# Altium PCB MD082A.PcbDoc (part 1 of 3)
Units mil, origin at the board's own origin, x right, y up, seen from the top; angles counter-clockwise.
Board outline 3650 x 4750 mil, 4 copper layers (Top Layer, GND Layer, Power Layer, Bottom Layer), stack 61.2 mil thick; 201 components, 105 nets, 514 pads, 1209 vias.
Unrouted connection lines stored in the file: 46.
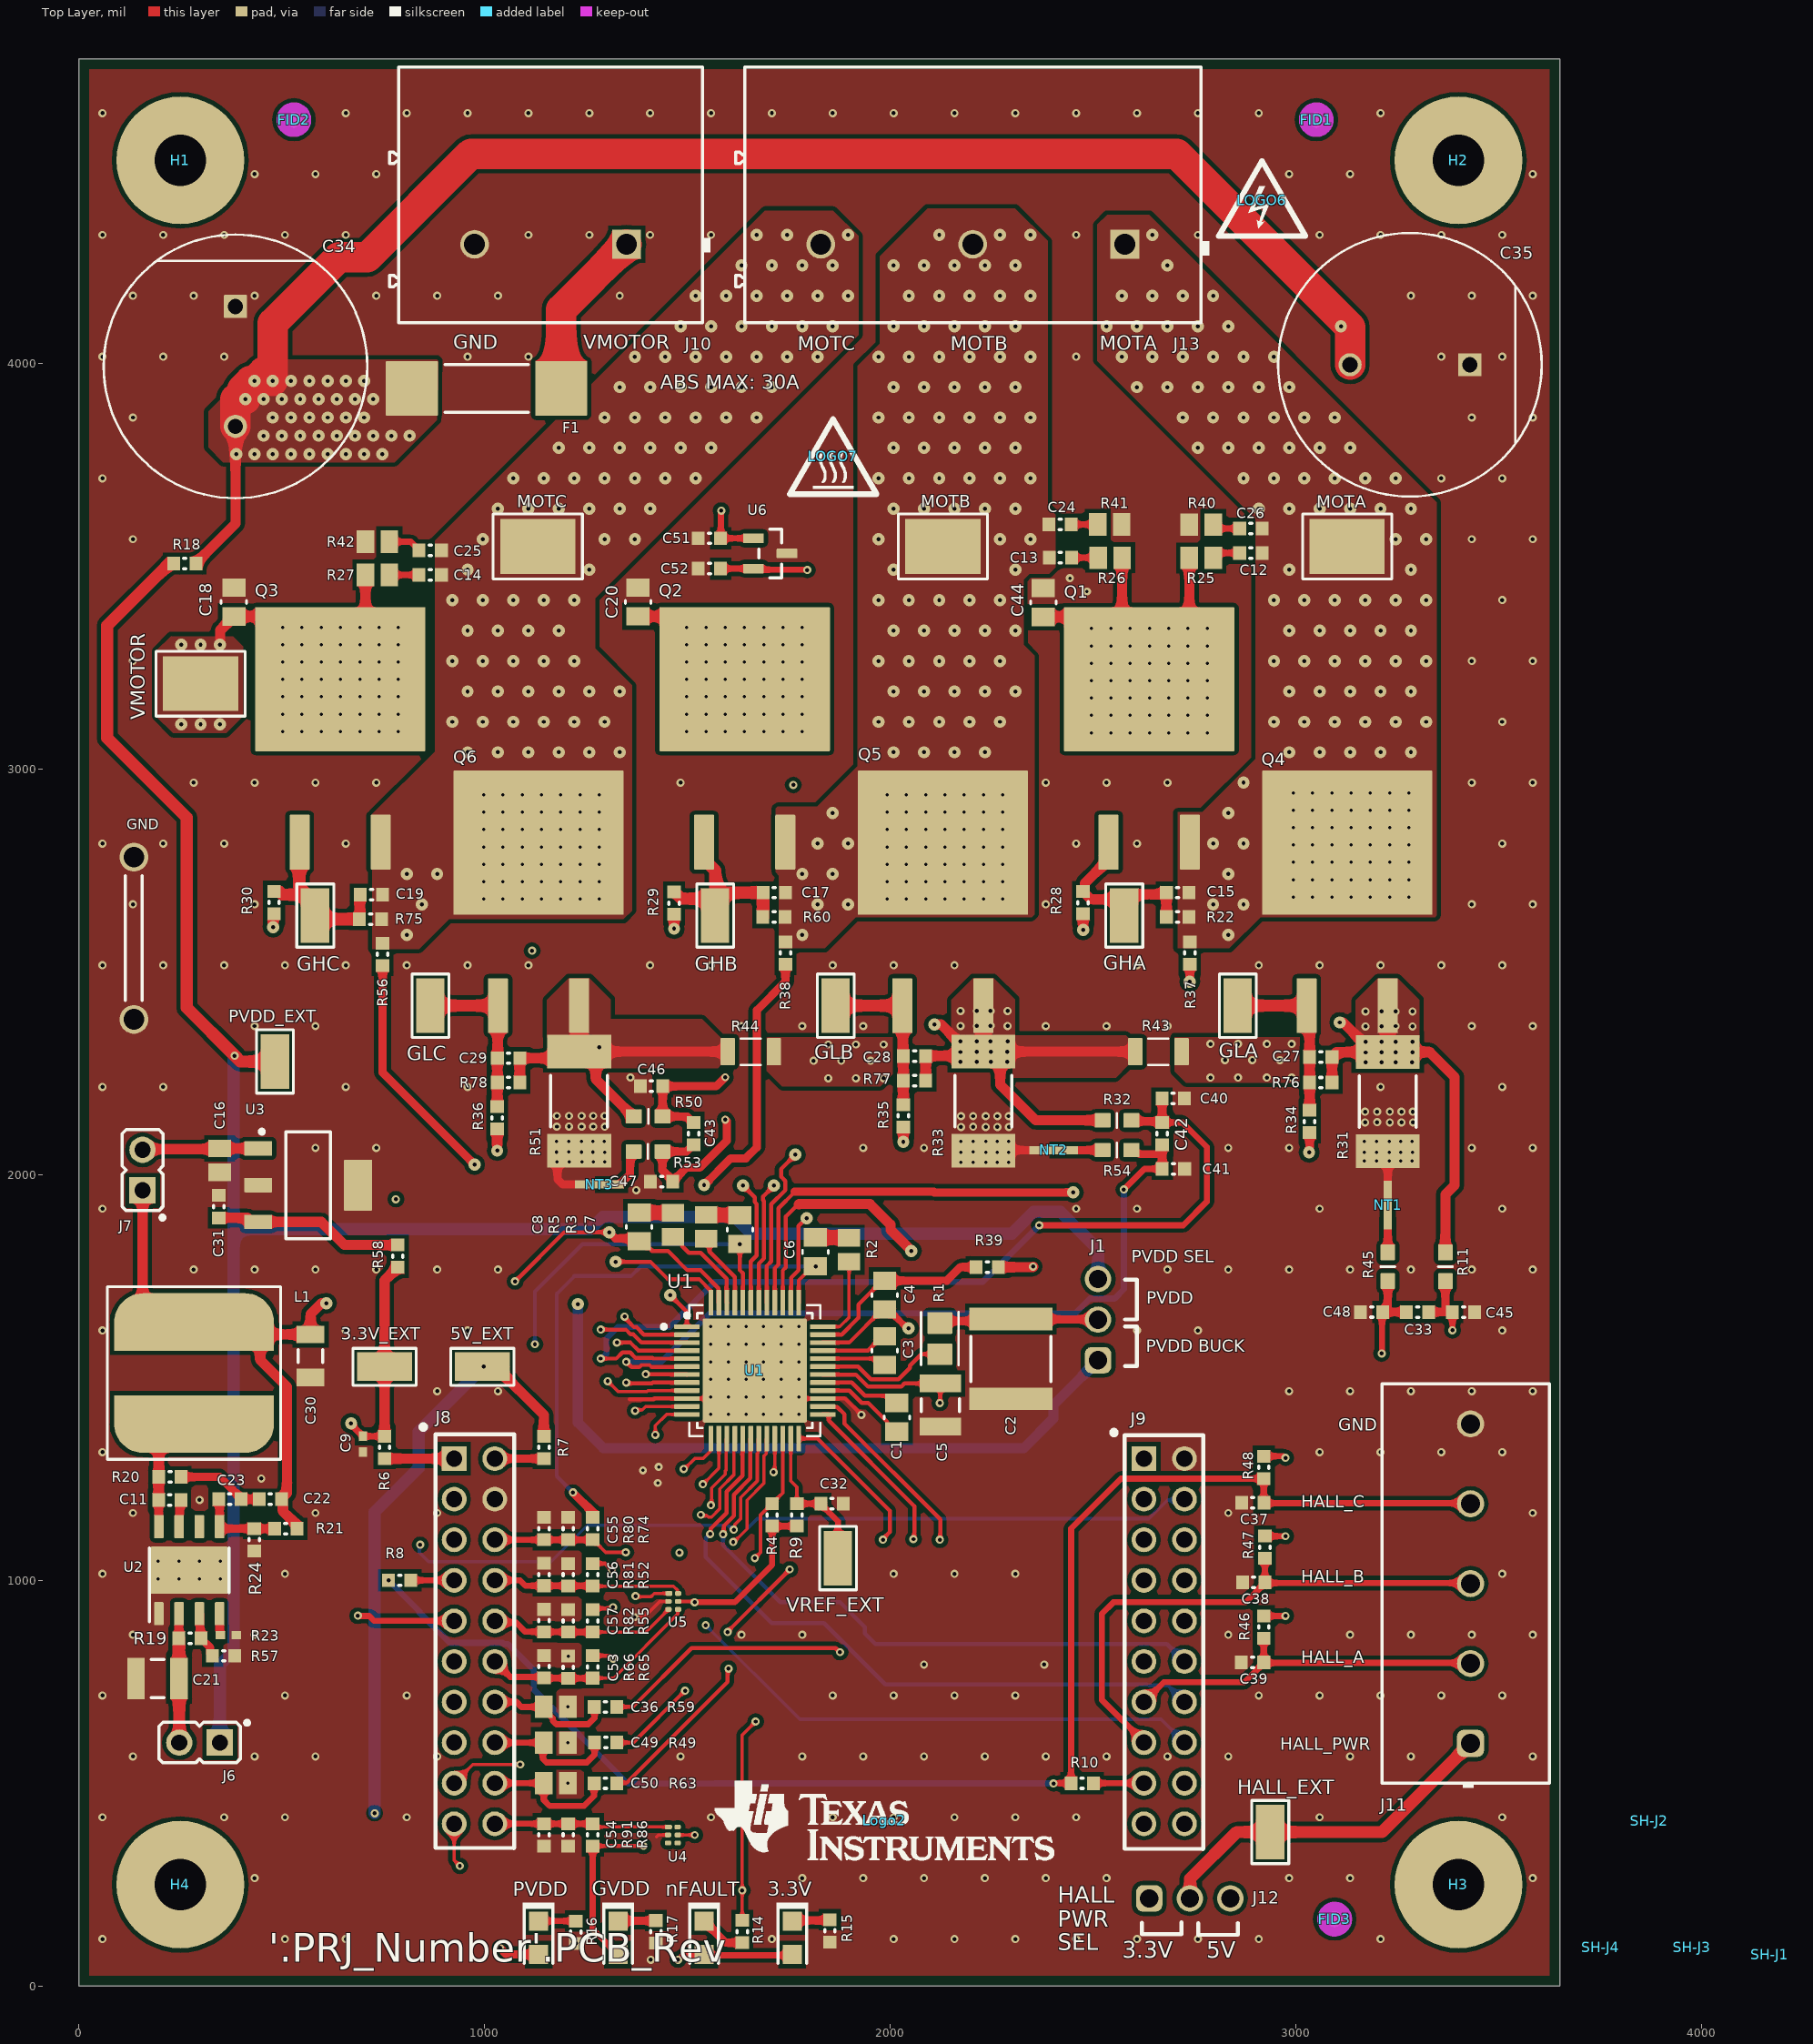
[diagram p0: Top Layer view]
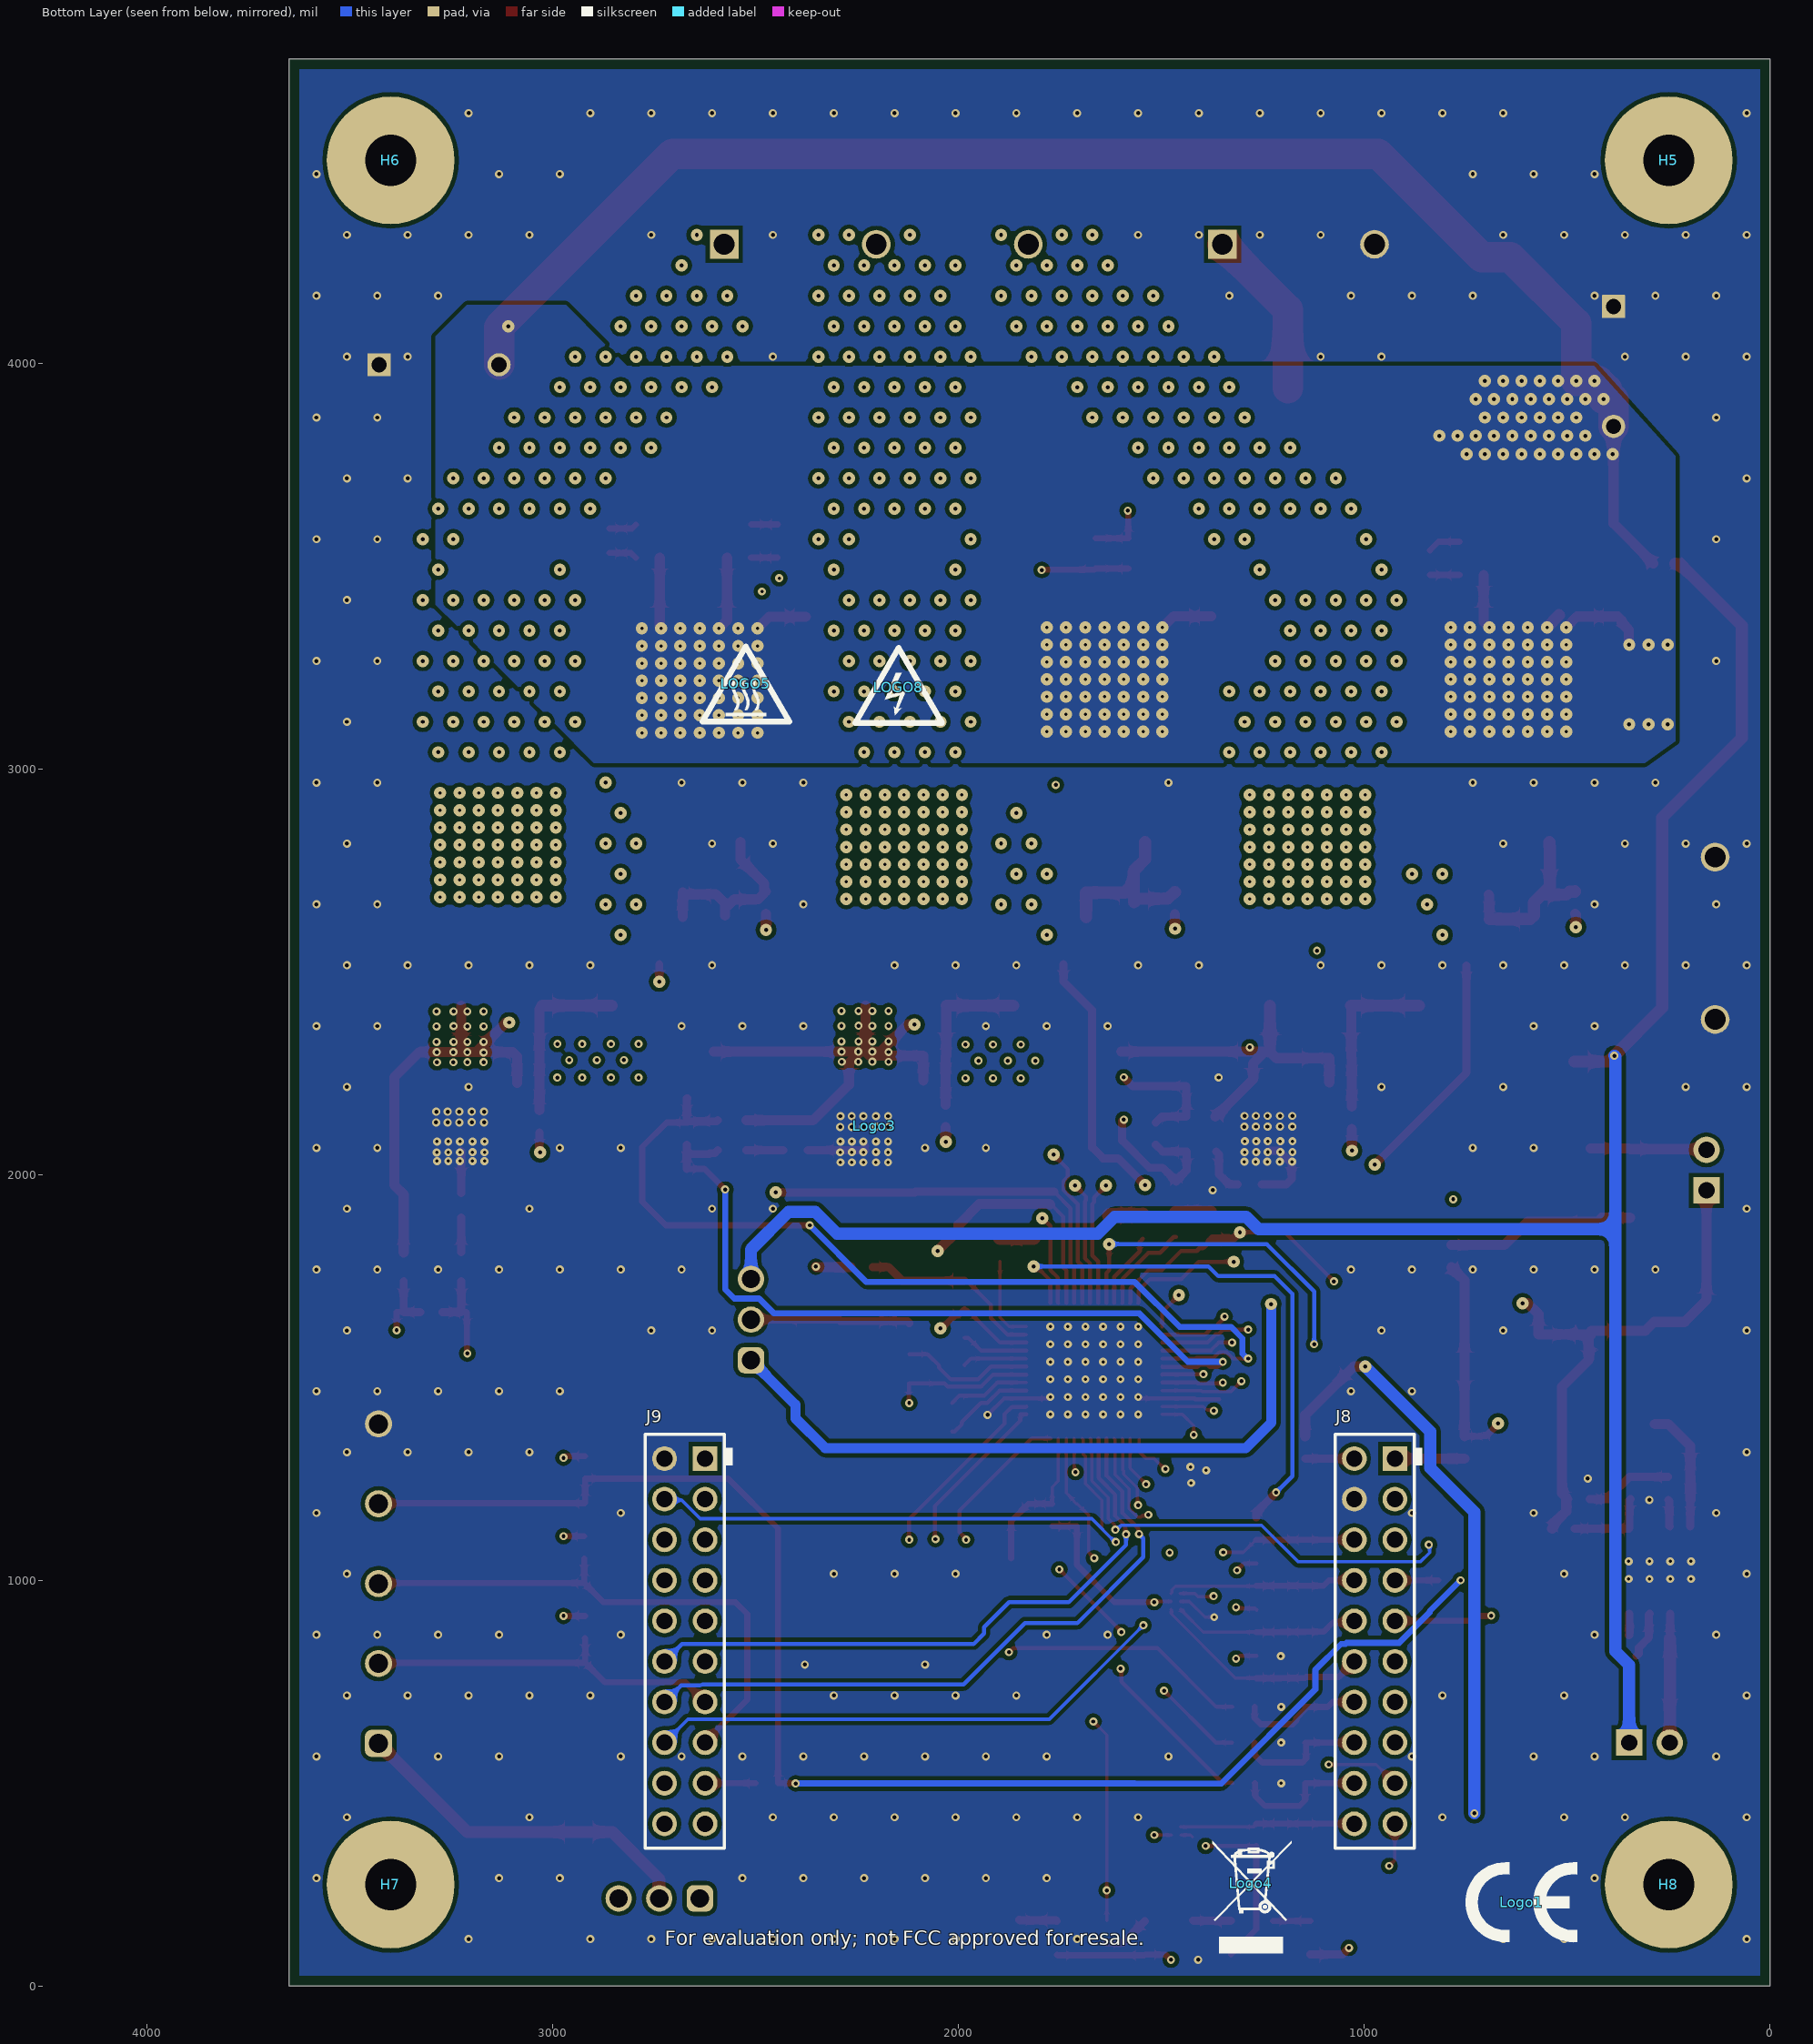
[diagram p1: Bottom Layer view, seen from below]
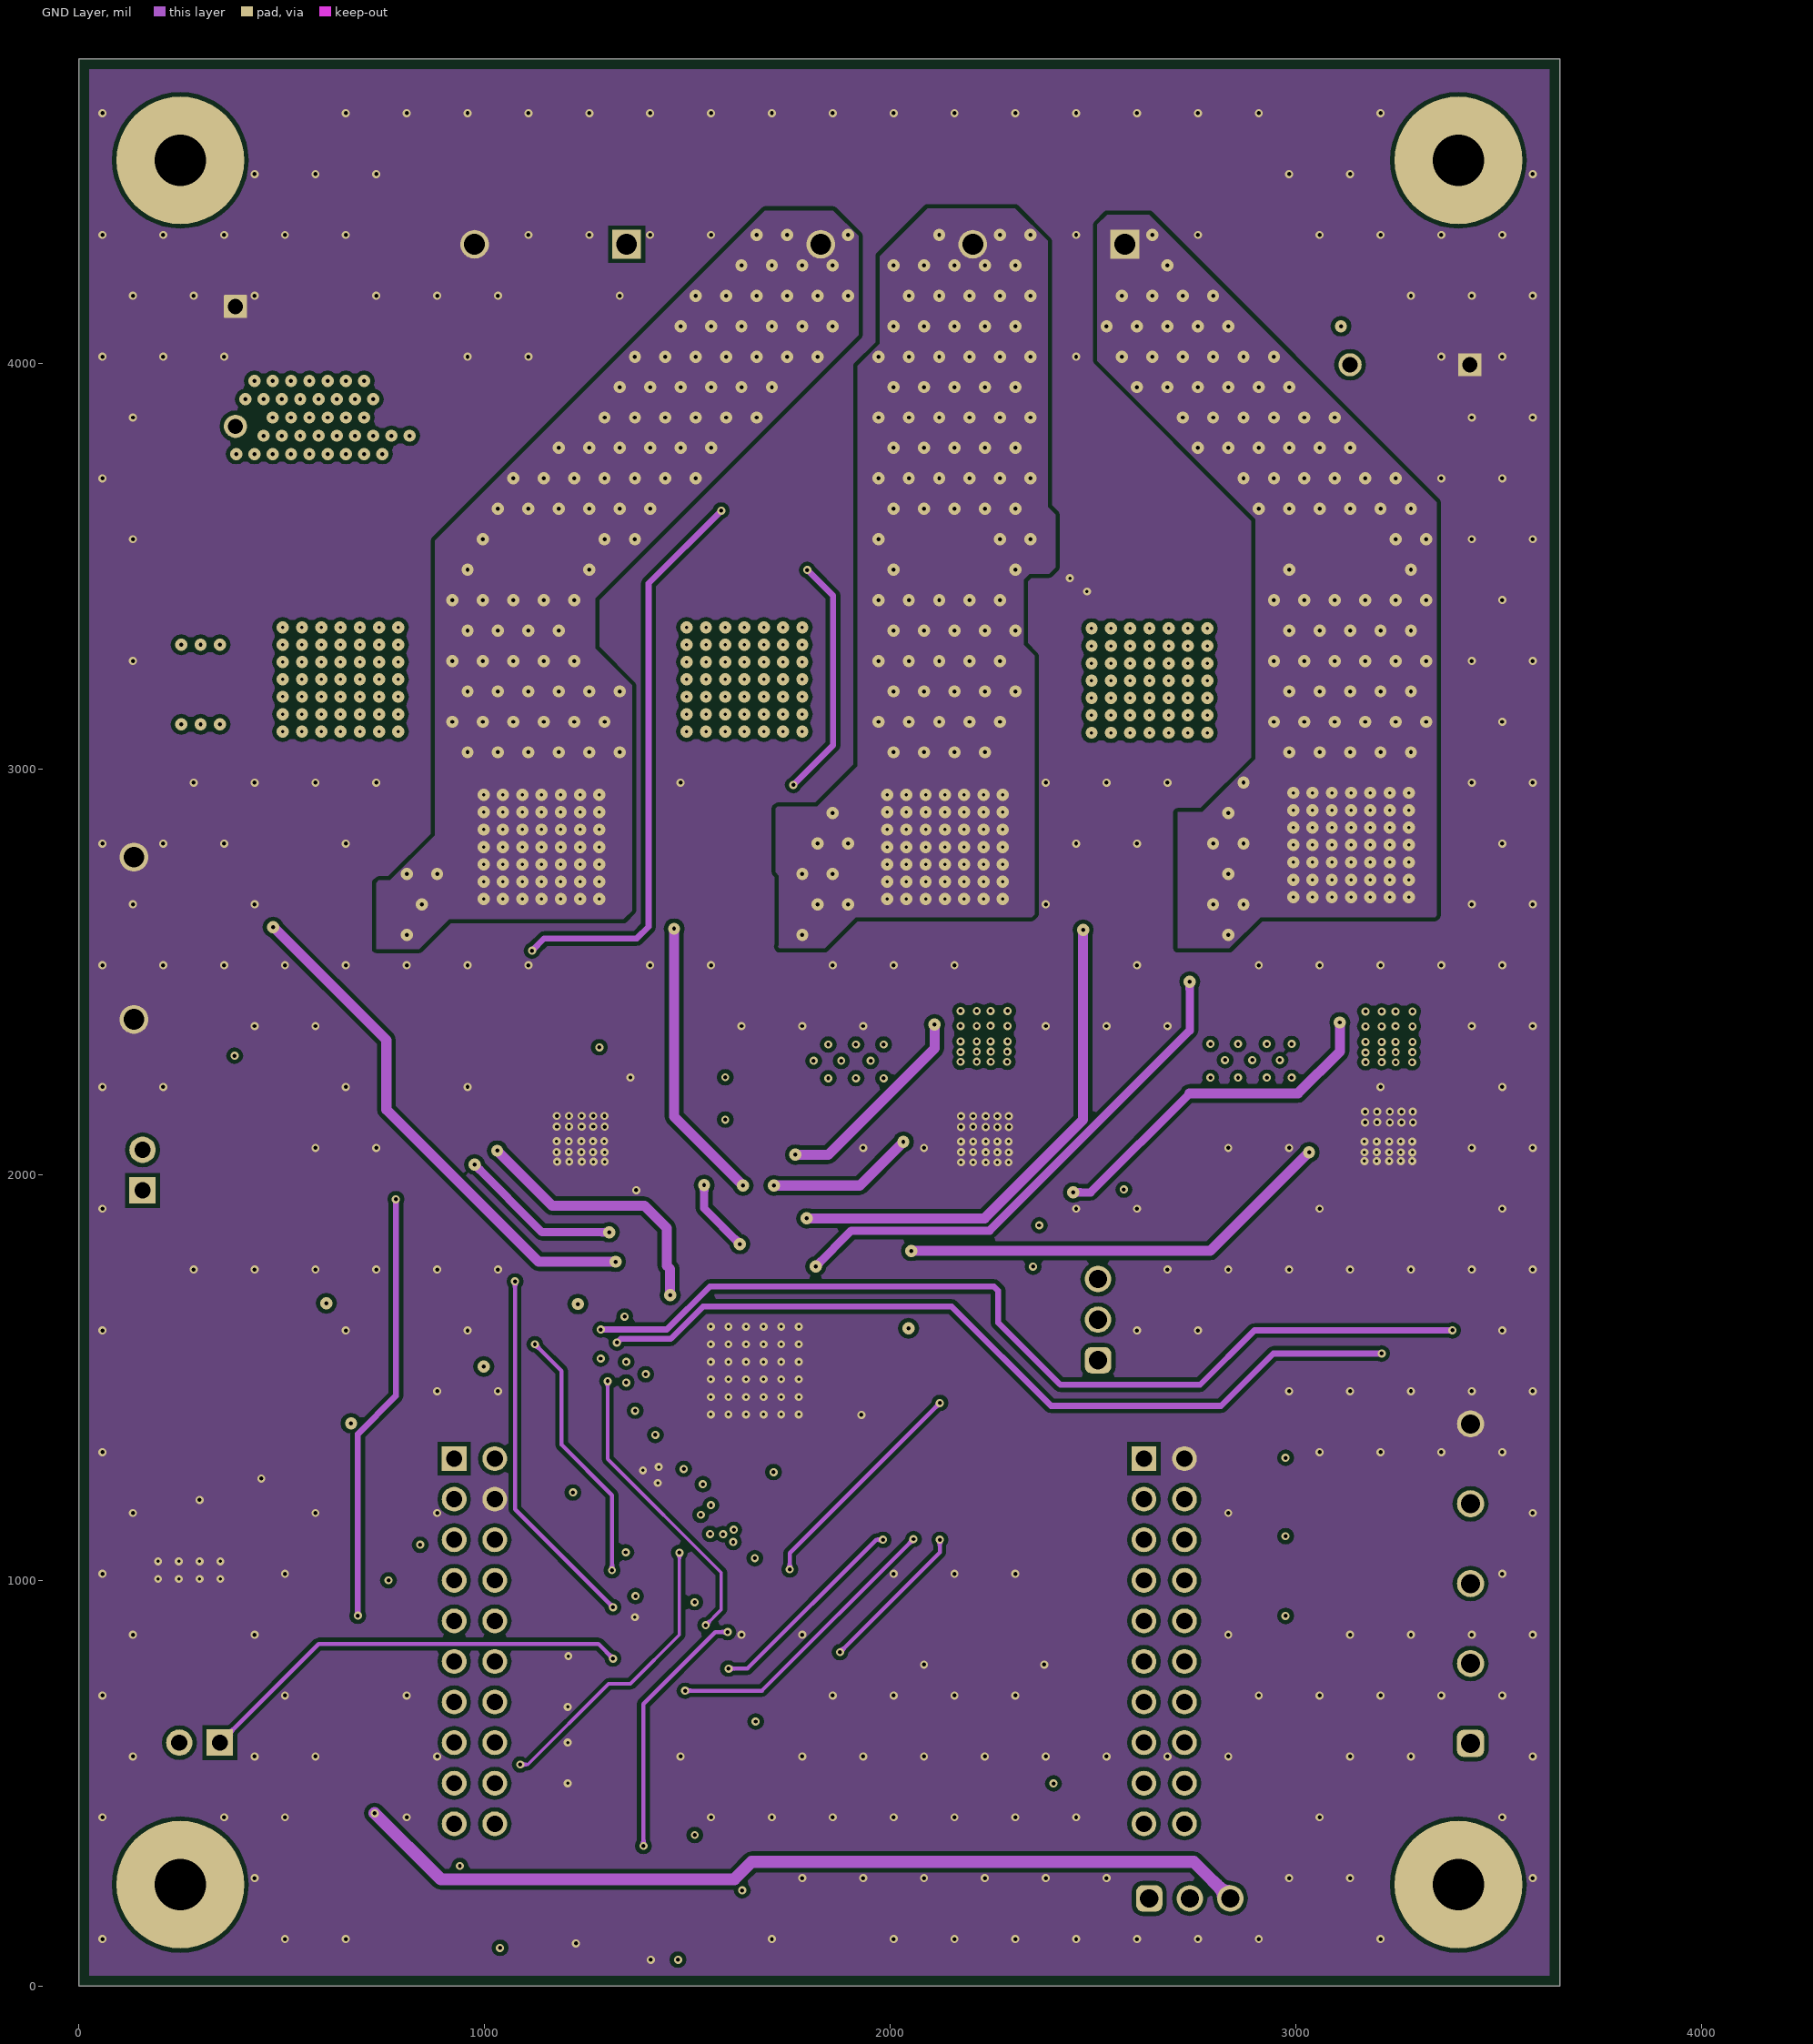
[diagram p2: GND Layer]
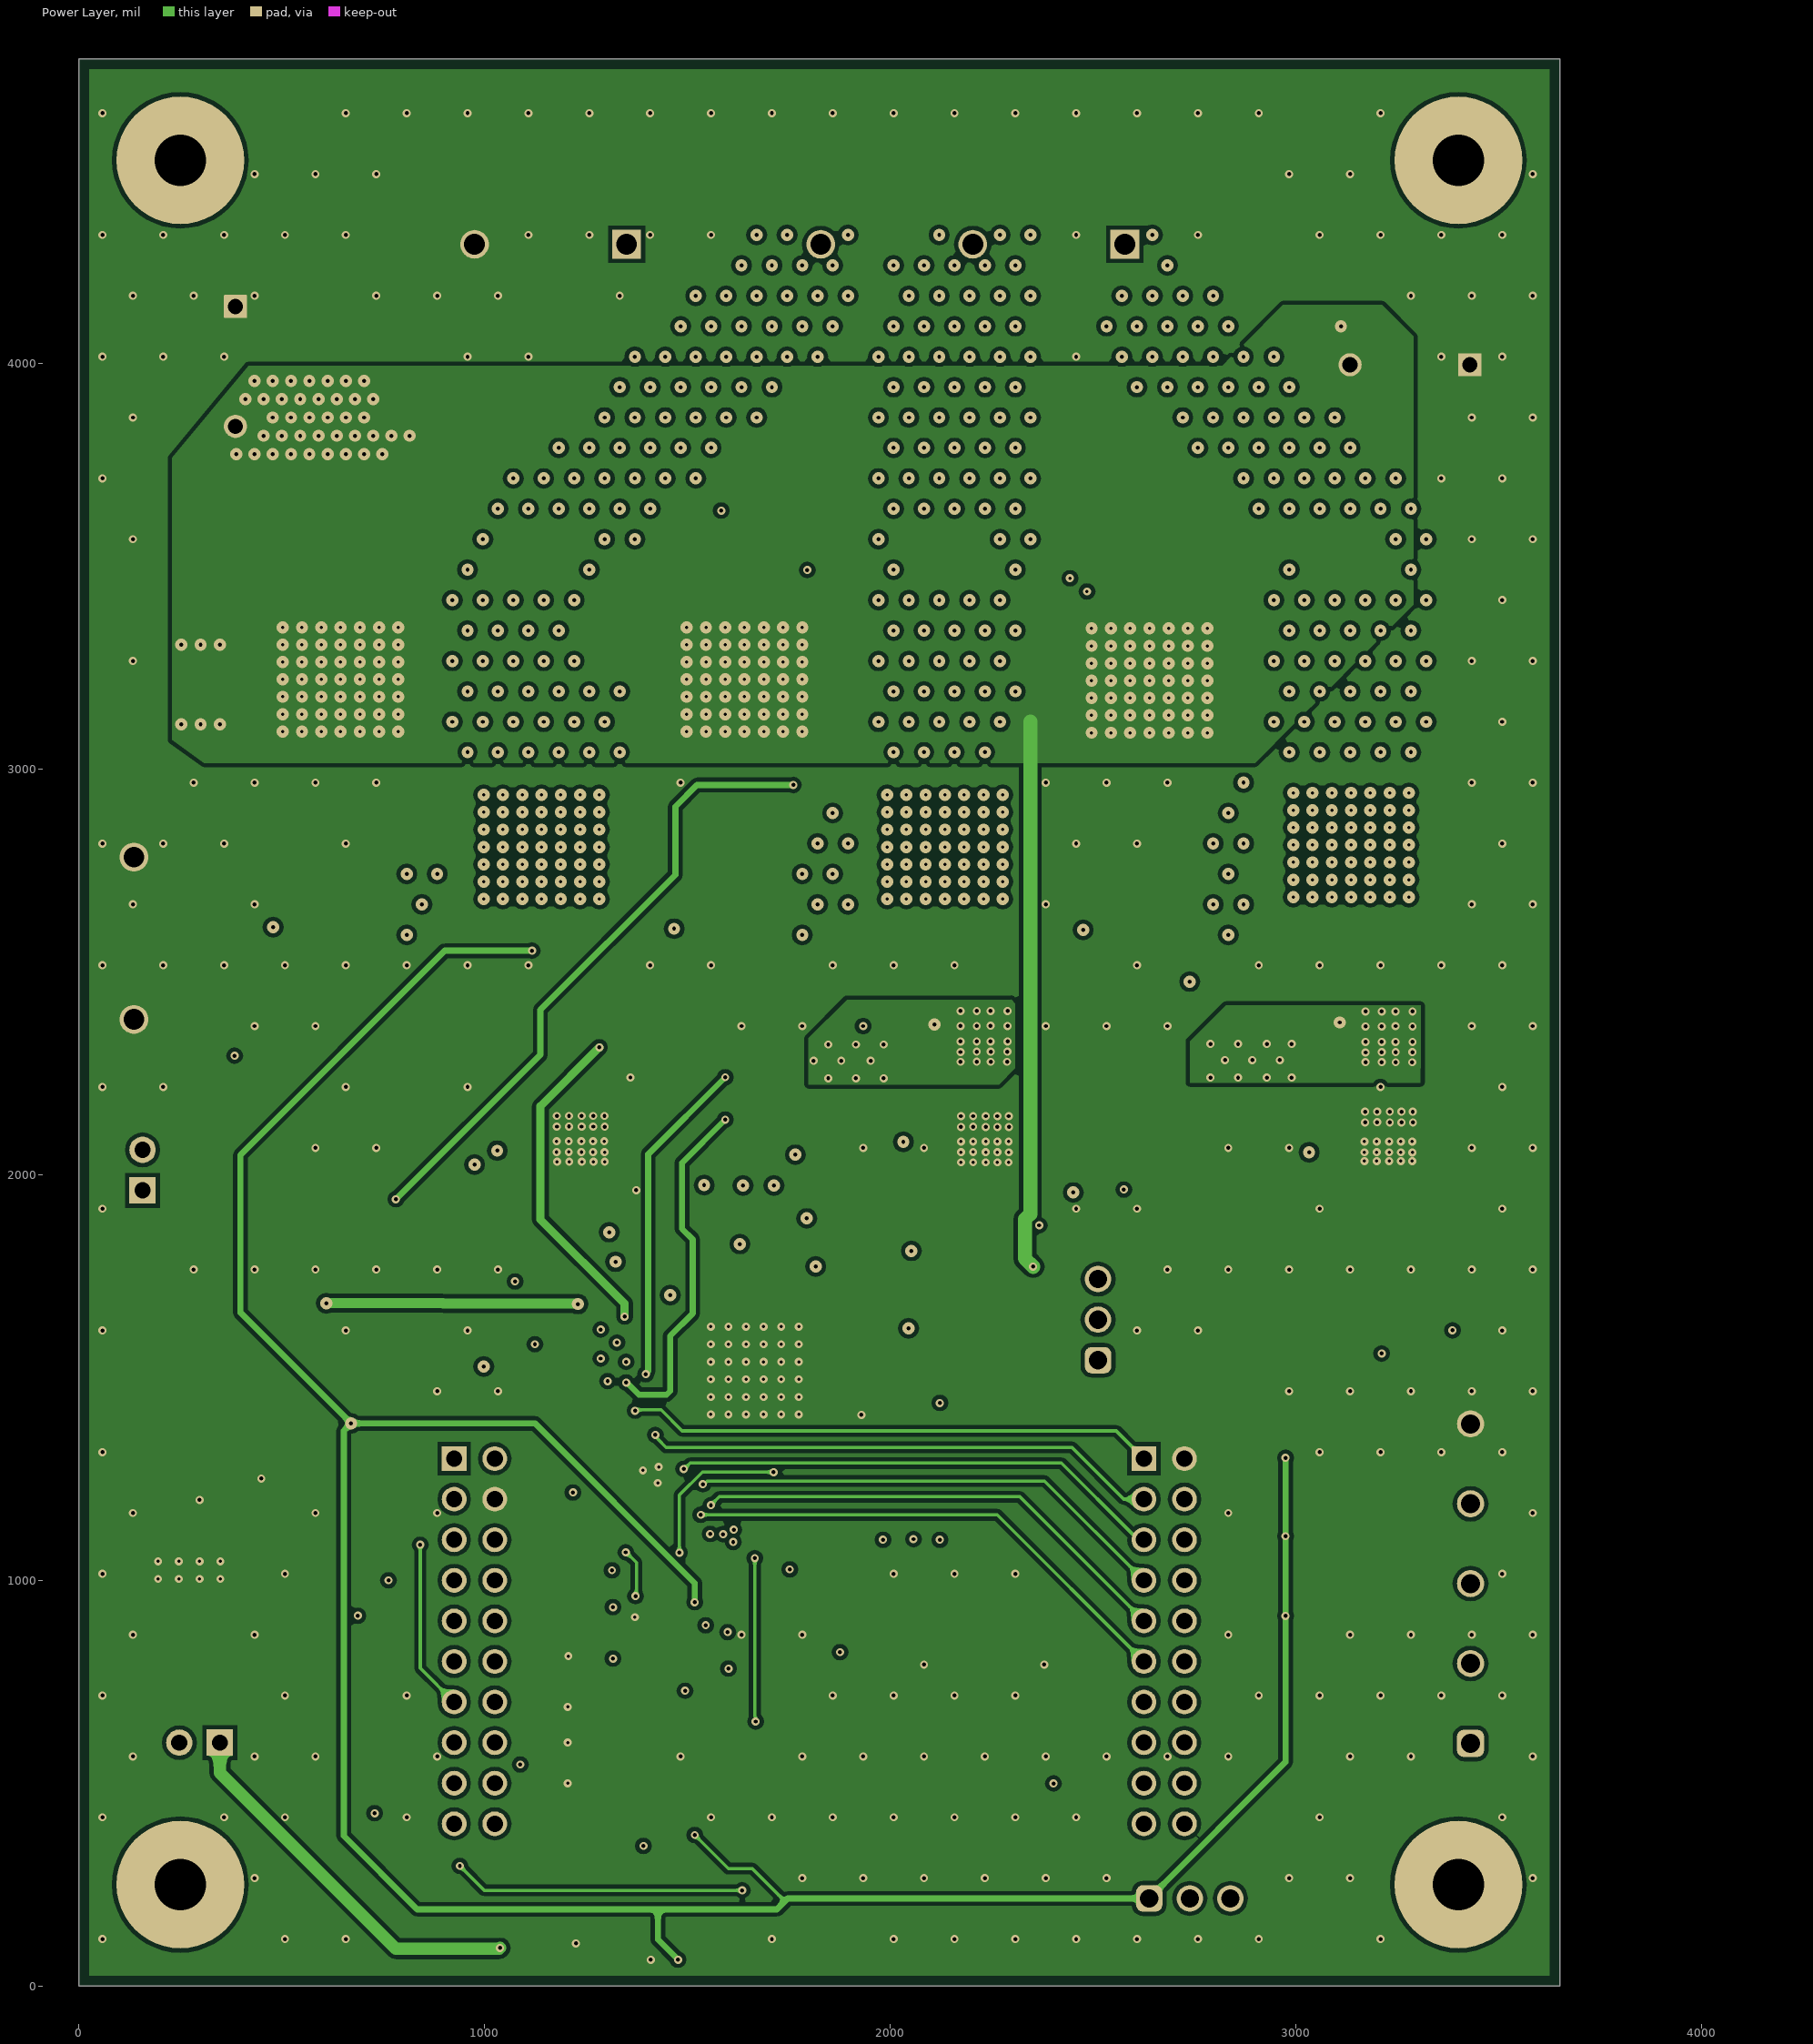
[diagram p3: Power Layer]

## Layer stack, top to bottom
Top Solder: solder mask 0.4, Solder Resist, Dk 3.5
Top Layer: signal copper 2.8
Dielectric 2: core 10, FR-4 High Tg, Dk 4.8
GND Layer: signal copper 1.4
Dielectric 1: prepreg 32.8, FR-4 High Tg, Dk 4.2
Power Layer: signal copper 1.4
Dielectric 3: core 10, FR-4 High Tg, Dk 4.8
Bottom Layer: signal copper 2.8
Solder Side: solder mask 0.4, Solder Resist, Dk 3.5

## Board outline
0,0 3650,0 3650,4750 0,4750

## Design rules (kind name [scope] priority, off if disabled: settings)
AcuteAngle [All] p1: minimum=4.50000000000000E+0001 checktracksonly=FALSE
AssemblyTestPointUsage [All] p1: valid=2
BoardOutlineClearance BoardOutlineClearance_MountingHoles [OnCopper and InComponentClass('Mounting Holes')] p1: gap=39.37 ignorepadtopadclearanceinfootprint=FALSE
BoardOutlineClearance BoardOutlineClearance_Poly [OnCopper and IsPoly] p2: gap=25 ignorepadtopadclearanceinfootprint=FALSE
BoardOutlineClearance [OnCopper and Not InComponentClass('Logo') and not InComponentClass('FiducialMark') and not InRegion(1000,500,4000,800) and not InPoly] p3: gap=50 ignorepadtopadclearanceinfootprint=FALSE
Clearance Clearance_Keepouts [((IsTrack Or IsArc) And Not InPoly) And IsFree and IsKeepOut vs ((IsTrack Or IsArc) And Not InPoly) And IsFree and IsKeepOut] p1: gap=0 ignorepadtopadclearanceinfootprint=FALSE
Clearance Clearance_Poly [InPolygon] p2: gap=10 ignorepadtopadclearanceinfootprint=TRUE
Clearance Clearance_FiducialMark [IsKeepOut and InComponentClass('FiducialMark') vs IsPad and InComponentClass('FiducialMark')] p3: gap=0 ignorepadtopadclearanceinfootprint=FALSE
Clearance [All] p4: gap=7.87 ignorepadtopadclearanceinfootprint=TRUE
ComponentClearance ComponentClearance_MountingHoles_FiducialMarks [InComponentClass('Mounting Holes') vs InComponentClass('FiducialMark')] p1: gap=50 collisioncheckmode=3 verticalgap=10 showdistances=FALSE
ComponentClearance ComponentClearance_Shunt [InComponentClass('Header') vs InComponentClass('Shunt')] p2: gap=0 collisioncheckmode=3 verticalgap=0 showdistances=FALSE
ComponentClearance ComponentClearance_Logo [InComponentClass('Logo')] p3: gap=20 collisioncheckmode=3 verticalgap=10 showdistances=FALSE
ComponentClearance ComponentClearance_ScrewToNut [(HasFootprint('NY PMS 440 0025 PH')) vs (HasFootprint('Keystone_1902C'))] p4: gap=5 collisioncheckmode=3 verticalgap=10 showdistances=FALSE
ComponentClearance ComponentClearance_MountingHoles [InComponentClass('Mounting Holes')] p5: gap=10 collisioncheckmode=3 verticalgap=100000 showdistances=FALSE
ComponentClearance ComponentClearance_SmallPassives [HasFootprint('0201*') or HasFootprint('0402*') or HasFootprint('0508') or HasFootprint('0603*') or HasFootprint('0612') or HasFootprint('0805*') or HasFootprint('0815*') or HasFootprint('0830*') or HasFootprint('1206*') or HasFootprint('1210*') or HasFootprint('1808*') or HasFootprint('1812*') or HasFootprint('1825*') or HasFootprint('2010*') or HasFootprint('2220*') or HasFootprint('2225*') or HasFootprint('2512*') or HasFootprint('2728*') or HasFootprint('3518*') vs HasFootprint('0201*') or HasFootprint('0402*') or HasFootprint('0508') or HasFootprint('0603*') or HasFootprint('0612') or HasFootprint('0805*') or HasFootprint('0815*') or HasFootprint('0830*') or HasFootprint('1206*') or HasFootprint('1210*') or HasFootprint('1808*') or HasFootprint('1812*') or HasFootprint('1825*') or HasFootprint('2010*') or HasFootprint('2220*') or HasFootprint('2225*') or HasFootprint('2512*') or HasFootprint('2728*') or HasFootprint('3518*')] p6: gap=14.96 collisioncheckmode=3 verticalgap=10 showdistances=FALSE
ComponentClearance ComponentClearance_THtoSMT [IsThruComponent vs IsSMTComponent] p7: gap=40 collisioncheckmode=3 verticalgap=30 showdistances=FALSE
ComponentClearance ComponentClearance_THtoTH [IsThruComponent vs IsThruComponent] p8: gap=30 collisioncheckmode=3 verticalgap=30 showdistances=FALSE
ComponentClearance [All] p9: gap=30 collisioncheckmode=3 verticalgap=10 showdistances=FALSE
DiffPairsRouting [All] p1: maxlimit=100 minlimit=10 mostfreqgap=10 toplayer_minwidth=15 toplayer_maxwidth=15 toplayer_prefwidth=15 midlayer1_minwidth=15 midlayer1_maxwidth=15 midlayer1_prefwidth=15 midlayer2_minwidth=15 midlayer2_maxwidth=15 midlayer2_prefwidth=15 bottomlayer_minwidth=15 bottomlayer_maxwidth=15 bottomlayer_prefwidth=15 maxuncoupledlength=1000
FabricationTestPointUsage TestPointUsage [All] p1: valid=2 allowmultiple=FALSE
FabricationTestpoint Testpoint [All] p1: side=3 testpointundercomponent=TRUE minsize=40 maxsize=100 preferedsize=60 minholesize=0 maxholesize=40 preferedholesize=32 testpointgrid=1 allowsidetop=TRUE allowsidebottom=TRUE usegrid=TRUE gridtolerance=0.01
FanoutControl Fanout_LCC [IsLCC] p1: bgadir=Out bgaviamode=Centered fanoutstyle=Auto fanoutdirection=Alternating viagrid=1 // Fanout_LCC (Default Rule)
FanoutControl Fanout_BGA [IsBGA] p2: bgadir=Out bgaviamode=Centered fanoutstyle=Auto fanoutdirection=Alternating viagrid=1 // Fanout_BGA (Default Rule)
FanoutControl Fanout_Default [All] p4: bgadir=Out bgaviamode=Centered fanoutstyle=Auto fanoutdirection=Alternating viagrid=1 // Fanout_Default (Default Rule)
FanoutControl Fanout_Small [(CompPinCount < 5)] p5: bgadir=Out bgaviamode=Centered fanoutstyle=Auto fanoutdirection=OutThenIn viagrid=1 // Fanout_Small (Default Rule)
Height [All] p1 off: minheight=0 maxheight=1000 prefheight=500
HoleSize [All] p1: absolutevalues=TRUE maxlimit=250 minlimit=7.8 maxpercent=80.000 minpercent=20.000
MinimumAnnularRing MinimumAnnularRing_ThermalPadVias [IsVia and InAnyComponent] p1: minimumring=5
MinimumAnnularRing [All] p2: minimumring=5
MinimumSolderMaskSliver MinimumSolderMaskSliver_Logo [InComponentClass('Logo') vs InComponentClass('Logo')] p1: minsoldermaskwidth=0.7
MinimumSolderMaskSliver [All] p2: minsoldermaskwidth=3.94
PlaneConnect [All] p1: planeconnectstyle=Direct reliefexpansion=10 reliefentries=4 reliefconductorwidth=10 reliefairgap=10
PolygonConnect PolygonConnect_57 [All] p1: connectstyle=Direct reliefconductorwidth=10 reliefentries=4 polygonreliefangle="90 Angle" airgapwidth=10
PolygonConnect PolygonConnect_56 [All vs IsNamedPolygon('Top Layer-MOTB')] p2: connectstyle=Direct reliefconductorwidth=10 reliefentries=4 polygonreliefangle="90 Angle" airgapwidth=10
PolygonConnect PolygonConnect_55 [All vs IsNamedPolygon('TOP_LAYER_SLB_P091')] p3: connectstyle=Direct reliefconductorwidth=10 reliefentries=4 polygonreliefangle="90 Angle" airgapwidth=10
PolygonConnect PolygonConnect_54 [All vs IsNamedPolygon('TOP_LAYER_SLC_P102')] p4: connectstyle=Direct reliefconductorwidth=10 reliefentries=4 polygonreliefangle="90 Angle" airgapwidth=10
PolygonConnect PolygonConnect_53 [All vs IsNamedPolygon('TOP_LAYER_SLC_P102')] p5: connectstyle=Direct reliefconductorwidth=10 reliefentries=4 polygonreliefangle="90 Angle" airgapwidth=10
PolygonConnect PolygonConnect_52 [All vs IsNamedPolygon('TOP_LAYER_SLB_P094')] p6: connectstyle=Direct reliefconductorwidth=10 reliefentries=4 polygonreliefangle="90 Angle" airgapwidth=10
PolygonConnect [All vs IsNamedPolygon('TOP_LAYER_SLA_P093')] p7: connectstyle=Direct reliefconductorwidth=10 reliefentries=4 polygonreliefangle="90 Angle" airgapwidth=10
PolygonConnect PolygonConnect_51 [All vs IsNamedPolygon('TOP_LAYER_NONET_P084')] p8: connectstyle=Direct reliefconductorwidth=10 reliefentries=4 polygonreliefangle="90 Angle" airgapwidth=10
PolygonConnect PolygonConnect_50 [All vs IsNamedPolygon('BOTTOM_LAYER_GND_P082')] p9: connectstyle=Direct reliefconductorwidth=10 reliefentries=4 polygonreliefangle="90 Angle" airgapwidth=10
PolygonConnect PolygonConnect_49 [All vs IsNamedPolygon('GND_LAYER_LSS_P072')] p10: connectstyle=Direct reliefconductorwidth=10 reliefentries=4 polygonreliefangle="90 Angle" airgapwidth=10
PolygonConnect PolygonConnect_48 [All vs IsNamedPolygon('POWER_LAYER_LSS_P076')] p11: connectstyle=Direct reliefconductorwidth=10 reliefentries=4 polygonreliefangle="90 Angle" airgapwidth=10
PolygonConnect PolygonConnect_47 [All vs IsNamedPolygon('GND_LAYER_LSS_P072')] p12: connectstyle=Direct reliefconductorwidth=10 reliefentries=4 polygonreliefangle="90 Angle" airgapwidth=10
PolygonConnect PolygonConnect_46 [All vs IsNamedPolygon('BOTTOM_LAYER_GND_P076')] p13: connectstyle=Direct reliefconductorwidth=10 reliefentries=4 polygonreliefangle="90 Angle" airgapwidth=10
PolygonConnect PolygonConnect_45 [All vs IsNamedPolygon('BOTTOM_LAYER_OUTA_P076')] p14: connectstyle=Direct reliefconductorwidth=10 reliefentries=4 polygonreliefangle="90 Angle" airgapwidth=10
PolygonConnect PolygonConnect_44 [All vs IsNamedPolygon('BOTTOM_LAYER_OUTB_P074')] p15: connectstyle=Direct reliefconductorwidth=10 reliefentries=4 polygonreliefangle="90 Angle" airgapwidth=10
PolygonConnect PolygonConnect_43 [All vs IsNamedPolygon('BOTTOM_LAYER_OUTC_P072')] p16: connectstyle=Direct reliefconductorwidth=10 reliefentries=4 polygonreliefangle="90 Angle" airgapwidth=10
PolygonConnect PolygonConnect_42 [All vs IsNamedPolygon('BOTTOM_LAYER_NONET_P070')] p17: connectstyle=Direct reliefconductorwidth=10 reliefentries=4 polygonreliefangle="90 Angle" airgapwidth=10
PolygonConnect PolygonConnect_41 [All vs IsNamedPolygon('POWER_LAYER_GND_P068')] p18: connectstyle=Direct reliefconductorwidth=10 reliefentries=4 polygonreliefangle="90 Angle" airgapwidth=10
PolygonConnect PolygonConnect_40 [All vs IsNamedPolygon('GND_LAYER_GND_P066')] p19: connectstyle=Direct reliefconductorwidth=10 reliefentries=4 polygonreliefangle="90 Angle" airgapwidth=10
PolygonConnect PolygonConnect_39 [All vs IsNamedPolygon('TOP_LAYER_GND_P070')] p20: connectstyle=Direct reliefconductorwidth=10 reliefentries=4 polygonreliefangle="90 Angle" airgapwidth=10
PolygonConnect PolygonConnect_38 [All vs IsNamedPolygon('BOTTOM_LAYER_GND')] p21: connectstyle=Direct reliefconductorwidth=10 reliefentries=4 polygonreliefangle="90 Angle" airgapwidth=10
PolygonConnect PolygonConnect_37 [All vs IsNamedPolygon('BOTTOM_LAYER_GND')] p22: connectstyle=Direct reliefconductorwidth=10 reliefentries=4 polygonreliefangle="90 Angle" airgapwidth=10
PolygonConnect PolygonConnect_36 [All vs IsNamedPolygon('GND_LAYER_OUTA_P060')] p23: connectstyle=Direct reliefconductorwidth=10 reliefentries=4 polygonreliefangle="90 Angle" airgapwidth=10
PolygonConnect PolygonConnect_35 [All vs IsNamedPolygon('GND_LAYER_OUTB_P058')] p24: connectstyle=Direct reliefconductorwidth=10 reliefentries=4 polygonreliefangle="90 Angle" airgapwidth=10
PolygonConnect PolygonConnect_34 [All vs IsNamedPolygon('GND_LAYER_OUTC_P056')] p25: connectstyle=Direct reliefconductorwidth=10 reliefentries=4 polygonreliefangle="90 Angle" airgapwidth=10
PolygonConnect PolygonConnect_33 [All vs IsNamedPolygon('POWER_LAYER_PVDD_P052')] p26: connectstyle=Direct reliefconductorwidth=10 reliefentries=4 polygonreliefangle="90 Angle" airgapwidth=10
PolygonConnect PolygonConnect_32 [All vs IsNamedPolygon('POWER_LAYER_PVDD_P052')] p27: connectstyle=Direct reliefconductorwidth=10 reliefentries=4 polygonreliefangle="90 Angle" airgapwidth=10
PolygonConnect PolygonConnect_31 [All vs IsNamedPolygon('POWER_LAYER_OUTA_P050')] p28: connectstyle=Direct reliefconductorwidth=10 reliefentries=4 polygonreliefangle="90 Angle" airgapwidth=10
PolygonConnect PolygonConnect_30 [All vs IsNamedPolygon('POWER_LAYER_OUTB_P048')] p29: connectstyle=Direct reliefconductorwidth=10 reliefentries=4 polygonreliefangle="90 Angle" airgapwidth=10
PolygonConnect PolygonConnect_29 [All vs IsNamedPolygon('POWER_LAYER_OUTC_P046')] p30: connectstyle=Direct reliefconductorwidth=10 reliefentries=4 polygonreliefangle="90 Angle" airgapwidth=10
PolygonConnect PolygonConnect_28 [All vs IsNamedPolygon('POWER_LAYER_AVDD_P062')] p31: connectstyle=Direct reliefconductorwidth=10 reliefentries=4 polygonreliefangle="90 Angle" airgapwidth=10
PolygonConnect PolygonConnect_27 [All vs IsNamedPolygon('SIGNAL_LAYER_1_OUTA_P060')] p32: connectstyle=Direct reliefconductorwidth=10 reliefentries=4 polygonreliefangle="90 Angle" airgapwidth=10
PolygonConnect PolygonConnect_26 [All vs IsNamedPolygon('SIGNAL_LAYER_1_OUTB_P058')] p33: connectstyle=Direct reliefconductorwidth=10 reliefentries=4 polygonreliefangle="90 Angle" airgapwidth=10
PolygonConnect PolygonConnect_25 [All vs IsNamedPolygon('SIGNAL_LAYER_1_OUTC_P056')] p34: connectstyle=Direct reliefconductorwidth=10 reliefentries=4 polygonreliefangle="90 Angle" airgapwidth=10
PolygonConnect PolygonConnect_24 [All vs IsNamedPolygon('SIGNAL_LAYER_2_PVDD_P054')] p35: connectstyle=Direct reliefconductorwidth=10 reliefentries=4 polygonreliefangle="90 Angle" airgapwidth=10
PolygonConnect PolygonConnect_23 [All vs IsNamedPolygon('SIGNAL_LAYER_2_PVDD_P052')] p36: connectstyle=Direct reliefconductorwidth=10 reliefentries=4 polygonreliefangle="90 Angle" airgapwidth=10
PolygonConnect PolygonConnect_22 [All vs IsNamedPolygon('SIGNAL_LAYER_2_OUTA_P050')] p37: connectstyle=Direct reliefconductorwidth=10 reliefentries=4 polygonreliefangle="90 Angle" airgapwidth=10
PolygonConnect PolygonConnect_21 [All vs IsNamedPolygon('SIGNAL_LAYER_2_OUTB_P048')] p38: connectstyle=Direct reliefconductorwidth=10 reliefentries=4 polygonreliefangle="90 Angle" airgapwidth=10
PolygonConnect PolygonConnect_20 [All vs IsNamedPolygon('SIGNAL_LAYER_2_OUTC_P046')] p39: connectstyle=Direct reliefconductorwidth=10 reliefentries=4 polygonreliefangle="90 Angle" airgapwidth=10
PolygonConnect PolygonConnect_19 [All vs IsNamedPolygon('TOP_LAYER_AVDD_P044')] p40: connectstyle=Direct reliefconductorwidth=10 reliefentries=4 polygonreliefangle="90 Angle" airgapwidth=10
PolygonConnect PolygonConnect_18 [All vs IsNamedPolygon('TOP_LAYER_PVDD_P034')] p41: connectstyle=Direct reliefconductorwidth=10 reliefentries=4 polygonreliefangle="90 Angle" airgapwidth=10
PolygonConnect PolygonConnect_17 [All vs IsNamedPolygon('SIGNAL_LAYER_1_OUTC_P036')] p42: connectstyle=Direct reliefconductorwidth=10 reliefentries=4 polygonreliefangle="90 Angle" airgapwidth=10
PolygonConnect PolygonConnect_16 [All vs IsNamedPolygon('TOP_LAYER_PVDD_P034')] p43: connectstyle=Direct reliefconductorwidth=10 reliefentries=4 polygonreliefangle="90 Angle" airgapwidth=10
PolygonConnect PolygonConnect_15 [All vs IsNamedPolygon('TOP_LAYER_LSS_P030')] p44: connectstyle=Direct reliefconductorwidth=10 reliefentries=4 polygonreliefangle="90 Angle" airgapwidth=10
PolygonConnect PolygonConnect_14 [All vs IsNamedPolygon('TOP_LAYER_GLC_FET_P024')] p45: connectstyle=Direct reliefconductorwidth=10 reliefentries=4 polygonreliefangle="90 Angle" airgapwidth=10
PolygonConnect PolygonConnect_13 [All vs IsNamedPolygon('TOP_LAYER_GLB_FET_P026')] p46: connectstyle=Direct reliefconductorwidth=10 reliefentries=4 polygonreliefangle="90 Angle" airgapwidth=10
PolygonConnect PolygonConnect_12 [All vs IsNamedPolygon('TOP_LAYER_GLA_FET_P028')] p47: connectstyle=Direct reliefconductorwidth=10 reliefentries=4 polygonreliefangle="90 Angle" airgapwidth=10
PolygonConnect PolygonConnect_11 [All vs IsNamedPolygon('TOP_LAYER_GHB_FET_P020')] p48: connectstyle=Direct reliefconductorwidth=10 reliefentries=4 polygonreliefangle="90 Angle" airgapwidth=10
PolygonConnect PolygonConnect_10 [All vs IsNamedPolygon('TOP_LAYER_GHA_FET_P022')] p49: connectstyle=Direct reliefconductorwidth=10 reliefentries=4 polygonreliefangle="90 Angle" airgapwidth=10
PolygonConnect PolygonConnect_9 [All vs IsNamedPolygon('TOP_LAYER_GHC_FET_P018')] p50: connectstyle=Direct reliefconductorwidth=10 reliefentries=4 polygonreliefangle="90 Angle" airgapwidth=10
PolygonConnect PolygonConnect_8 [All vs IsNamedPolygon('TOP_LAYER_GND_P014')] p51: connectstyle=Direct reliefconductorwidth=10 reliefentries=4 polygonreliefangle="90 Angle" airgapwidth=10
PolygonConnect PolygonConnect_7 [All vs IsNamedPolygon('TOP_LAYER_GND_P014')] p52: connectstyle=Direct reliefconductorwidth=10 reliefentries=4 polygonreliefangle="90 Angle" airgapwidth=10
PolygonConnect PolygonConnect_6 [All vs IsNamedPolygon('TOP_LAYER_PVDD_P008')] p53: connectstyle=Direct reliefconductorwidth=10 reliefentries=4 polygonreliefangle="90 Angle" airgapwidth=10
PolygonConnect PolygonConnect_5 [All vs IsNamedPolygon('TOP_LAYER_PVDD_P008')] p54: connectstyle=Direct reliefconductorwidth=10 reliefentries=4 polygonreliefangle="90 Angle" airgapwidth=10
PolygonConnect PolygonConnect_4 [All vs IsNamedPolygon('TOP_LAYER_PVDD_P008')] p55: connectstyle=Direct reliefconductorwidth=10 reliefentries=4 polygonreliefangle="90 Angle" airgapwidth=10
PolygonConnect PolygonConnect_3 [All vs IsNamedPolygon('TOP_LAYER_OUTA_P006')] p56: connectstyle=Direct reliefconductorwidth=10 reliefentries=4 polygonreliefangle="90 Angle" airgapwidth=10
PolygonConnect PolygonConnect_2 [All vs IsNamedPolygon('TOP_LAYER_OUTB_P004')] p57: connectstyle=Direct reliefconductorwidth=10 reliefentries=4 polygonreliefangle="90 Angle" airgapwidth=10
PolygonConnect PolygonConnect_1 [All vs IsNamedPolygon('TOP_LAYER_OUTC_P002')] p58: connectstyle=Direct reliefconductorwidth=10 reliefentries=4 polygonreliefangle="90 Angle" airgapwidth=10
RoutingVias ThermalPadVias [IsVia and InAnyComponent] p1 off: holewidth=7.87 width=19.68 viastyle="Through Hole" minholewidth=7.87 minwidth=19.68 maxholewidth=12.99 maxwidth=23.62
RoutingVias [All] p2 off: holewidth=10 width=20 viastyle="Through Hole" minholewidth=10 minwidth=20 maxholewidth=10 maxwidth=20
SilkToBoardRegionClearance [Not ((IsComment or IsDesignator) And (Hide <> 'False')) and not InRegion(1000,500,4000,800)] p1:
SilkToSilkClearance SilkToSilkClearance_Pb-FreeLogo [(HasFootprint('Pb-Free_Overlay_Medium') OR HasFootprint('Pb-Free_Overlay_Small')) vs (HasFootprint('Pb-Free_Overlay_Medium') OR HasFootprint('Pb-Free_Overlay_Small'))] p1: silktosilkclearance=0
SilkToSilkClearance [All] p2: silktosilkclearance=1
SilkToSolderMaskClearance SilkToComponentPadClearance [(IsPad or IsFill or IsRegion) and InAnycomponent] p1: minsilkscreentomaskgap=2 clearancetoexposedcopper=TRUE
SilkToSolderMaskClearance "Silk to Solder Mask Opening" [All] p2: minsilkscreentomaskgap=3.94 clearancetoexposedcopper=FALSE
SolderMaskExpansion [All] p1: expansion=1.97
UnRoutedNet [All] p1: checkbadconnections=TRUE
Width [All] p1: maxlimit=100 minlimit=6 preferedwidth=10 checkconnectedcopper=TRUE
13 further rules are at their usual default settings.

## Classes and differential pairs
component class "Mounting Holes": H5 H6 H7 H8
component class MD082A_Power: 3.3V C11 C16 C21 C22 C23 C30 C31 C37 C38 C39 F1 GND GVDD HALL_EXT J6 J7 J10 J11 J12 L1 nFAULT PVDD R14 R15 R16 R17 R19 R20 R21 R23 R24 R46 R47 R48 R57 R58 SH-J2 SH-J3 SH-J4 U2 U3 U4 U5
component class Shunt: SH-J1 SH-J2 SH-J3 SH-J4
component class MD082A_SenseFeedback: C36 C49 C50 C51 C52 C53 C54 C55 C56 C57 GND1 GND2 GND3 R49 R52 R55 R59 R63 R65 R66 R74 R80 R81 R82 R86 R91 U6
component class MD082A_HalfBridges: C12 C13 C14 C15 C17 C18 C19 C20 C24 C25 C26 C27 C28 C29 C33 C34 C35 C40 C41 C42 C43 C44 C45 C46 C47 C48 GHA GHB GHC GLA GLB GLC J13 MOTA MOTB MOTC NT1 NT2 NT3 PVDD_EXT Q1 Q2 Q3 Q4 Q5 Q6 R11 R18 R22 R25 R26 R27 R28 R29 R30 R31 R32 R33 R34 R35 R36 R37 R38 R39 R40 R41 R42 R43 R44 R45 R50 R51 R53 R54 R56 R60 R75 R76 R77 R78 VMOTOR
component class MD082A_Driver: 3.3V_EXT 5V_EXT C1 C2 C3 C4 C5 C6 C7 C8 C9 C32 J1 J8 J9 R1 R2 R3 R4 R5 R6 R7 R8 R9 R10 SH-J1 U1 VREF_EXT
component class Header: J1 J6 J7 J12
component class Logo: Logo2
component class MD082A_Hardware: FID1 FID2 FID3 H1 H2 H3 H4 H5 H6 H7 H8 Logo1 Logo2 Logo3 Logo4 LOGO5 LOGO6 LOGO7 LOGO8 ZZ1 ZZ2 ZZ3 ZZ4
component class FiducialMark: FID1 FID2 FID3
component class AssemblyNote: ZZ1 ZZ2 ZZ3 ZZ4

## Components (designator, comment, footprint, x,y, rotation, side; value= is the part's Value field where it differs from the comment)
3.3V "" LED_LTST-C171 1758.43,119 r90 top value=Green
3.3V_EXT "5015" Testpoint_Keystone_Miniature 753.44,1526.84 r0 top
5V_EXT "5015" Testpoint_Keystone_Miniature 994.49,1526.84 r0 top
C1 "KAF21KR72A105KU" 0805_150 2016.1,1401.91 r270 top value=1uF
C2 "CGA9N3X7S2A106K230KE" 2220_280L 2297,1545.57 r270 top value=10uF
C3 "KAF21KR72A105KU" 0805_150 1986,1566.21 r270 top value=1uF
C4 "KAF21KR72A105KU" 0805_150 1986,1703 r90 top value=1uF
C5 "CL32B106KBJNNWE" 1210_270L 2123,1432 r270 top value=10uF
C6 "KAF21KR72A105KU" 0805_150 1815.15,1809.81 r90 top value=1uF
C7 "KAF21KR72A105KU" 0805_150 1629.31,1864.21 r90 top value=1uF
C8 "KAF21KR72A105KU" 0805_150 1380.86,1871.21 r90 top value=1uF
C9 "C1005X5R1A225K050BC" 0402L 700.08,1335.43 r90 top value=2.2uF
C11 "CGA3E2X7R2A222K080AA" 0603L 224,1198 r180 top value=2200pF
C12 "GRM188R72A222KA01D" 0603L 2888.56,3532.2 r0 top value=2200pF
C13 "GRM188R72A222KA01D" 0603L 2419.25,3520.55 r180 top value=2200pF
C14 "GRM188R72A222KA01D" 0603L 866,3478 r0 top value=2200pF
C15 "06031C222KAT2A" 0603L 2708,2695 r0 top value=2200pF
C16 "KGM21AR51E334KU" 0805L 347,2035 r270 top value=0.33uF
C17 "06031C222KAT2A" 0603L 1714,2695 r0 top value=2200pF
C18 "KAF21KR72A105KU" 0805_150 382,3411 r270 top value=1uF
C19 "06031C222KAT2A" 0603L 721,2690 r0 top value=2200pF
C20 "KAF21KR72A105KU" 0805_150 1378,3411.43 r270 top value=1uF
C21 "C1210C225K1RAC7800" 1210_210L 193.85,758 r180 top value=2.2uF
C22 "CGA3E2X7R2A222K080AA" 0603L 472,1200 r180 top value=2200pF
C23 "GRM1885C2A560JA01D" 0603L 372,1200 r180 top value=56pF
C24 "GRM188R72A222KA01D" 0603L 2418.44,3602.45 r0 top value=2200pF
C25 "GRM188R72A222KA01D" 0603L 866,3538.25 r180 top value=2200pF
C26 "GRM188R72A222KA01D" 0603L 2888.56,3592.45 r180 top value=2200pF
C27 "06031C222KAT2A" 0603L 3061,2290 r0 top value=2200pF
C28 "06031C222KAT2A" 0603L 2059.56,2292 r0 top value=2200pF
C29 "06031C222KAT2A" 0603L 1059,2287 r0 top value=2200pF
C30 "C3216X5R1E476M160AC" 1206_190L 571,1553 r270 top value=47uF
C31 "C0603C104J4RAC7867" 0603L 345,1921 r90 top value=0.1uF
C32 "C0603C104J4RAC7867" 0603L 1856.47,1188.72 r0 top value=0.1uF
C33 "885012206034" 0603L 3299.5,1661.17 r180 top value=1000pF
C34 "ESH477M100AM2AA" FP-ESH477M100AM2AA_RADIAL-MFG 386,3992 r270 top value=470µF
C35 "ESH477M100AM2AA" FP-ESH477M100AM2AA_RADIAL-MFG 3280.64,3996 r180 top value=470µF
C36 "C0805C471K5RAC7800" 0805L 1175.53,688.06 r0 top value=470pF
C37 "885012206034" 0603L 2893.1,1191.55 r180 top value=1000pF
C38 "885012206034" 0603L 2895.58,994.7 r180 top value=1000pF
C39 "885012206034" 0603L 2892.78,797.85 r180 top value=1000pF
C40 "885012206034" 0603L 2696.96,2187.73 r0 top value=1000pF
C41 "885012206034" 0603L 2697.78,2014.09 r0 top value=1000pF
C42 "885012206034" 0603L 2670.23,2100.91 r270 top value=1000pF
C43 "885012206034" 0603L 1514.98,2100.9 r270 top value=1000pF
C44 "KAF21KR72A105KU" 0805_150 2377,3410 r270 top value=1uF
C45 "885012206034" 0603L 3412.9,1661.17 r0 top value=1000pF
C46 "885012206034" 0603L 1411.42,2217.66 r180 top value=1000pF
C47 "885012206034" 0603L 1436.21,1982.61 r180 top value=1000pF
C48 "885012206034" 0603L 3186.11,1661.37 r180 top value=1000pF
C49 "C0805C471K5RAC7800" 0805L 1175.53,600 r0 top value=470pF
C50 "C0805C471K5RAC7800" 0805L 1175.53,500 r0 top value=470pF
C51 "C0603C104J4RAC7867" 0603L 1553.91,3568.4 r180 top value=0.1uF
C52 "C0603C104J4RAC7867" 0603L 1553.91,3493.6 r180 top value=0.1uF
C53 "C0603C104K5RACAUTO" 0603L 1146,787.37 r270 top value=0.1uF
C54 "C0603C104K5RACAUTO" 0603L 1146,372.44 r90 top value=0.1uF
C55 "C0603C104K5RACAUTO" 0603L 1146,1127.56 r270 top value=0.1uF
C56 "C0603C104K5RACAUTO" 0603L 1146,1014.16 r270 top value=0.1uF
C57 "C0603C104K5RACAUTO" 0603L 1146,900.77 r270 top value=0.1uF
F1 "100VDC 30A" Fuse_0463 1004.75,3938 r0 top
FID1 "Fiducial" Fiducial10-20 3050,4600 r0 top
FID2 "Fiducial" Fiducial10-20 530,4600 r0 top
FID3 "Fiducial" Fiducial10-20 3095,165 r0 top
GHA "5015" Testpoint_Keystone_Miniature 2576.15,2638.45 r90 top
GHB "5015" Testpoint_Keystone_Miniature 1568.15,2638.45 r90 top
GHC "5015" Testpoint_Keystone_Miniature 582.15,2638.45 r90 top
GLA "5015" Testpoint_Keystone_Miniature 2856,2416.43 r90 top
GLB "5015" Testpoint_Keystone_Miniature 1865.21,2416.43 r90 top
GLC "5015" Testpoint_Keystone_Miniature 866,2416.43 r90 top
GND "D3082-05" Harwin_D3082-05 135.58,2582.56 r90 top
GVDD "" LED_LTST-C171 1329,119 r90 top value=Green
H1 "1902E" Keystone_1902E 250,4500 r0 top
H2 "1902E" Keystone_1902E 3400,4500 r0 top
H3 "1902E" Keystone_1902E 3400,250 r0 top
H4 "1902E" Keystone_1902E 250,250 r0 top
H5 "NY PMS 440 0025 PH" "NY PMS 440 0025 PH" 250,4500 r180 bottom
H6 "NY PMS 440 0025 PH" "NY PMS 440 0025 PH" 3400,4500 r180 bottom
H7 "NY PMS 440 0025 PH" "NY PMS 440 0025 PH" 3400,250 r180 bottom
H8 "NY PMS 440 0025 PH" "NY PMS 440 0025 PH" 250,250 r180 bottom
HALL_EXT "5015" Testpoint_Keystone_Miniature 2935.94,379.57 r90 top
J1 "61300311121" WURTH_61300311121 2512,1642.58 r90 top
J6 "PBC02SAAN" Sullins_PBC02SAAN 297.59,600 r270 top
J7 "PBC02SAAN" Sullins_PBC02SAAN 157,2011 r180 top
J8 "SSQ-110-03-G-D" Samtec_SSQ-110-03-x-D 975,850 r270 bottom
J9 "SSQ-110-03-G-D" Samtec_SSQ-110-03-x-D 2675,850 r270 bottom
J10 "VMOTOR INPUT" Phoenix_1902547 1162.6,4415.05 r180 top
J11 "HALL IN" Phoenix_1792892 3430,991.85 r90 top
J12 "61300311121" WURTH_61300311121 2738,216 r0 top
J13 "Motor OUT" Phoenix_1904150 2203.2,4415.05 r180 top
L1 "SDR1006-680KL" SDR1006 284,1510.98 r90 top value=68uH
Logo1 "CE Mark" CE_Mark_5mm 613,206.56 r180 bottom
Logo2 "Texas Instruments" TI_Stacked_Overlay_Small 1985.39,408 r0 top
Logo3 "FCC disclaimer" FCC_disclaimer 2208,2120 r180 bottom
Logo4 "WEEE logo" WEEE_Minimum 1279.29,253.52 r180 bottom
LOGO5 "CAUTION HOT SURFACE" IEC_HotSurface_Small 2524.5,3209.5 r180 bottom
LOGO6 "DANGER HIGH VOLTAGE" IEC_HighVoltage_Small 2916,4401 r0 top
LOGO7 "CAUTION HOT SURFACE" IEC_HotSurface_Small 1859,3769.81 r0 top
LOGO8 "DANGER HIGH VOLTAGE" IEC_HighVoltage_Small 2148,3201 r180 bottom
MOTA "5016" Testpoint_Keystone_Compact 3126,3548 r0 top
MOTB "5016" Testpoint_Keystone_Compact 2129.5,3548 r0 top
MOTC "5016" Testpoint_Keystone_Compact 1131,3548 r0 top
nFAULT "" LED_LTST-C170_Red 1541,119 r90 top value=Red
NT1 "Net-Tie" Net-Tie_20milWide_60milLong 3226,1924.64 r90 top net-tie
NT2 "Net-Tie" Net-Tie_20milWide_60milLong 2402.31,2060.39 r180 top net-tie
NT3 "Net-Tie" Net-Tie_20milWide_60milLong 1282.75,1975.64 r180 top net-tie
PVDD "" LED_LTST-C171 1133.2,119 r90 top value=Green
PVDD_EXT "5015" Testpoint_Keystone_Miniature 483.08,2278.69 r90 top
Q1 "STH310N10F7-2" DDPAK 2638,3065.49 r90 top value=100V
Q2 "STH310N10F7-2" DDPAK 1641,3065.49 r90 top value=100V
Q3 "STH310N10F7-2" DDPAK 644,3065.49 r90 top value=100V
Q4 "STH310N10F7-2" DDPAK 3126,2662.49 r90 top value=100V
Q5 "STH310N10F7-2" DDPAK 2129.5,2662.49 r90 top value=100V
Q6 "STH310N10F7-2" DDPAK 1133,2662.49 r90 top value=100V
R1 "RL1220S-R75-F" FP-RL1220S-R75-F_0805-IPC_A 2122,1595.8 r270 top value=0.75
R2 "CRCW08052R70JNEA" 0805L 1898.43,1814.81 r270 top value=2.7
R3 "CRCW08052R70JNEA" 0805L 1546.04,1871.21 r270 top value=2.7
R4 "CRCW060310K0JNEA" 0603L 1708.63,1161.16 r90 top value=10k
R5 "CRCW08052R70JNEA" 0805L 1464.14,1876.21 r270 top value=2.7
R6 "RCS06030000Z0EA" 0603L 753.44,1327.56 r270 top value=0
R7 "RCS06030000Z0EA" 0603L 1146,1327.56 r90 top value=0
R8 "RCS06030000Z0EA" 0603L 790.66,1000 r0 top value=0
R9 "RCS06030000Z0EA" 0603L 1769.65,1161.16 r90 top value=0
R10 "RCS06030000Z0EA" 0603L 2473,500 r0 top value=0
R11 "CPF-A-0603B10RE" FP-CPF-A-0603B10RE_0603-MFG 3367.99,1772.87 r90 top value=10
R14 "CRCW0603330RJNEA" 0603L 1635,134.44 r270 top value=330
R15 "CRCW0603330RJNEA" 0603L 1851,136 r90 top value=330
R16 "CRCW06034K99FKEA" 0603L 1225.23,132.78 r90 top value=4.99k
R17 "CRCW06034K99FKEA" 0603L 1422,134 r90 top value=4.99k
R18 "RCS06030000Z0EA" 0603L 261,3506 r180 top value=0
R19 "CRCW06031M00JNEA" 0603L 274,857 r180 top value=1.0Meg
R20 "RC0603FR-07681KL" 0603L 224.44,1255 r0 top value=681k
R21 "RC0603FR-07453KL" 0603L 510,1127 r0 top value=453k
R22 "CRCW0603100KFKEA" 0603L 2708,2634.75 r0 top value=100k
R23 "CRCW0402100KFKED" 0402L 368,865 r180 top value=100k
R24 "RC0603FR-0749K9L" 0603L 432.03,1100 r90 top value=49.9k
R25 "CRCW08052R70JNEA" 0805L 2766.3,3520.1 r180 top value=2.7
R26 "CRCW08052R70JNEA" 0805L 2541.51,3520.55 r0 top value=2.7
R27 "CRCW08052R70JNEA" 0805L 735.83,3478 r180 top value=2.7
R28 "RCS06030000Z0EA" 0603L 2475,2670 r90 top value=0
R29 "RCS06030000Z0EA" 0603L 1467,2669 r90 top value=0
R30 "RCS06030000Z0EA" 0603L 481,2670.73 r90 top value=0
R31 "CRE2512-FZ-R005E-3" CRE2512-R5_R9 3226,2180 r90 top value=0.005
R32 "CPF-A-0603B10RE" FP-CPF-A-0603B10RE_0603-MFG 2558.52,2133.8 r180 top value=10
R33 "CRE2512-FZ-R005E-3" CRE2512-R5_R9 2229.5,2181 r90 top value=0.005
R34 "RCS06030000Z0EA" 0603L 3033.44,2131 r90 top value=0
R35 "RCS06030000Z0EA" 0603L 2032,2144.93 r90 top value=0
R36 "RCS06030000Z0EA" 0603L 1031,2139.93 r90 top value=0
R37 "RCS06030000Z0EA" 0603L 2738,2546 r90 top value=0
R38 "RCS06030000Z0EA" 0603L 1741.56,2546 r90 top value=0
R39 "RCS06030000Z0EA" 0603L 2239,1772 r0 top value=0
R40 "CRCW08052R70JNEA" 0805L 2766.3,3602 r0 top value=2.7
R41 "CRCW08052R70JNEA" 0805L 2540.7,3602.45 r180 top value=2.7
R42 "CRCW08052R70JNEA" 0805L 735.83,3559.9 r0 top value=2.7
R43 "CRCW12060000Z0EAC" FP-CRCW12060000Z0EAC_1206-MFG 2660.66,2303.05 r180 top value=0
R44 "CRCW12060000Z0EAC" FP-CRCW12060000Z0EAC_1206-MFG 1656.16,2303.05 r180 top value=0
R45 "CPF-A-0603B10RE" FP-CPF-A-0603B10RE_0603-MFG 3226,1773.07 r90 top value=10
R46 "CRCW060310K0JNEA" 0603L 2920.34,884.67 r270 top value=10k
R47 "CRCW060310K0JNEA" 0603L 2923.14,1081.52 r270 top value=10k
R48 "CRCW060310K0JNEA" 0603L 2920.34,1278.37 r270 top value=10k
R49 "RT0603DRE07160RL" 0603L 1298.56,600 r0 top value=160
R50 "CPF-A-0603B10RE" FP-CPF-A-0603B10RE_0603-MFG 1403.27,2143.35 r180 top value=10
R51 "CRE2512-FZ-R005E-3" CRE2512-R5_R9 1233,2181 r90 top value=0.005
R52 "CRCW060397K6FKEA" 0603L 1266.49,1013.92 r90 top value=97.6k
R53 "CPF-A-0603B10RE" FP-CPF-A-0603B10RE_0603-MFG 1402.77,2056.91 r180 top value=10
R54 "CPF-A-0603B10RE" FP-CPF-A-0603B10RE_0603-MFG 2558.52,2060.39 r180 top value=10
R55 "CRCW060397K6FKEA" 0603L 1266.49,900 r90 top value=97.6k
R56 "RCS06030000Z0EA" 0603L 748.56,2542.93 r90 top value=0
R57 "CRCW0603330KJNEA" 0603L 357,814 r180 top value=330k
R58 "CRCW06030000Z0EA" 0603L 785.95,1799 r270 top value=0
R59 "RT0603DRE07160RL" 0603L 1297.78,688.06 r0 top value=160
R60 "CRCW0603100KFKEA" 0603L 1713.44,2634.75 r0 top value=100k
R63 "RT0603DRE07160RL" 0603L 1297.78,500 r0 top value=160
R65 "CRCW060397K6FKEA" 0603L 1266.49,786.6 r90 top value=97.6k
R66 "CRCW06033K01FKEA" 0603L 1206.25,785.71 r270 top value=3.01k
R74 "CRCW060397K6FKEA" 0603L 1266.49,1127.56 r90 top value=97.6k
R75 "CRCW0603100KFKEA" 0603L 719,2629.75 r0 top value=100k
R76 "CRCW0603100KFKEA" 0603L 3061,2226.56 r0 top value=100k
R77 "CRCW0603100KFKEA" 0603L 2059.56,2231.75 r0 top value=100k
R78 "CRCW0603100KFKEA" 0603L 1059,2226.75 r0 top value=100k
R80 "CRCW06033K01FKEA" 0603L 1206.25,1127.56 r270 top value=3.01k
R81 "CRCW06033K01FKEA" 0603L 1206.25,1013.92 r270 top value=3.01k
R82 "CRCW06033K01FKEA" 0603L 1206.25,900 r270 top value=3.01k
R86 "CRCW060397K6FKEA" 0603L 1266.49,372.44 r270 top value=97.6k
R91 "CRCW06033K01FKEA" 0603L 1206.25,372.44 r90 top value=3.01k
SH-J1 "SNT-100-BK-G" SNT-100-BK-G 4168,78 r270 top value=1x2
SH-J2 "SNT-100-BK-G" SNT-100-BK-G 3871,407.31 r270 top value=1x2
SH-J3 "SNT-100-BK-G" SNT-100-BK-G 3976,95 r90 top value=1x2
SH-J4 "SNT-100-BK-G" SNT-100-BK-G 3751,95 r90 top value=1x2
U1 "DRV8334PHPR" PHP0048P-MFG 1666,1517 r0 top
U1 "DRV3233EPHPRQ1" 0-MFG 1666,1517 r0 top
U2 "LM5164DDAT" DDA0008E_N 272,1025 r90 top
U3 "UA78M33CDCYR" DCY0004A_N 565,1974 r0 top
U4 "TPD4S009DRYR" DRY0006A 1464,372.38 r0 top
U5 "TPD4S009DRYR" DRY0006A 1465,948 r0 top
U6 "TMP235A2DBZR" DBZ0003A-MFG 1704,3531 r0 top
VMOTOR "5016" Testpoint_Keystone_Compact 300,3210 r180 top
VREF_EXT "5015" Testpoint_Keystone_Miniature 1870.79,1054.57 r90 top
ZZ1 "This Assembly Note is for PCB labels only" AssemblyNoteLabel 4947.75,2186.47 r90 top
ZZ2 "These assemblies are ESD sensitive, ESD precautions shall be observed." AssemblyNote 4770.59,4666.77 r90 top
ZZ3 "These assemblies must be clean and free from flux and all contaminants. Use of no clean flux is not acceptable." AssemblyNote 4593.42,3121.5 r90 top
ZZ4 "These assemblies must comply with workmanship standards IPC-A-610 Class 2, unless otherwise specified." AssemblyNote 4416.26,3446.31 r90 top

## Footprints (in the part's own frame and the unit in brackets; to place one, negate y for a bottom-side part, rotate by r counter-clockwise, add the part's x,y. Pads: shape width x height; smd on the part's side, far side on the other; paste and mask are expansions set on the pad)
0-MFG [mm]
  rrect33% 1.6x0.3 smd paste+0 mask+0: 1(-4.25,2.75) 2(-4.25,2.25) 3(-4.25,1.75) 4(-4.25,1.25) 5(-4.25,0.75) 6(-4.25,0.25) 7(-4.25,-0.25) 8(-4.25,-0.75) 9(-4.25,-1.25) 10(-4.25,-1.75) 11(-4.25,-2.25) 12(-4.25,-2.75) 25(4.25,-2.75) 26(4.25,-2.25) 27(4.25,-1.75) 28(4.25,-1.25) 29(4.25,-0.75) 30(4.25,-0.25) 31(4.25,0.25) 32(4.25,0.75) 33(4.25,1.25) 34(4.25,1.75) 35(4.25,2.25) 36(4.25,2.75)
  rrect33% 0.3x1.6 smd paste+0 mask+0: 13(-2.75,-4.25) 14(-2.25,-4.25) 15(-1.75,-4.25) 16(-1.25,-4.25) 17(-0.75,-4.25) 18(-0.25,-4.25) 19(0.25,-4.25) 20(0.75,-4.25) 21(1.25,-4.25) 22(1.75,-4.25) 23(2.25,-4.25) 24(2.75,-4.25) 37(2.75,4.25) 38(2.25,4.25) 39(1.75,4.25) 40(1.25,4.25) 41(0.75,4.25) 42(0.25,4.25) 43(-0.25,4.25) 44(-0.75,4.25) 45(-1.25,4.25) 46(-1.75,4.25) 47(-2.25,4.25) 48(-2.75,4.25)
  rrect2% 6.5x6.5 smd paste-1000 mask-1000: 49(0,0)
  silkscreen extent -4.37,-3.6 3.6,3.6, body extent -5.15,-5.15 5.15,5.15, height 0.25
0402L [mm] "0402 from SM-752 data"
  rect 0.6x0.5 smd: 1(-0.5,0) 2(0.5,0)
  body extent -0.55,-0.3 0.55,0.3, height 0.6
0603L [mm] "0603 from SM-752 data"
  rect 0.8x0.85 smd: 1(-0.7,0) 2(0.7,0)
  silkscreen extent -0.07,-0.33 0.07,0.33, body extent -0.87,-0.47 0.87,0.47, height 1
0805_150 [mm] "0805 / 1.5 mm height"
  rect 1.15x1.45 smd: 1(-0.9,0) 2(0.9,0)
  silkscreen extent -0.1,-0.8 0.1,0.8, body extent -1.1,-0.72 1.1,0.72, height 1.5
0805L [mm] "0805 from SM-752 data"
  rect 1.1x1.4 smd: 1(-0.75,0) 2(0.75,0)
  body extent -1.1,-0.72 1.1,0.72, height 1.45
1206_190L [mm] "1206_190"
  rect 1.1x1.75 smd: 1(-1.35,0) 2(1.35,0)
  silkscreen extent -0.4,-0.77 0.4,0.77, body extent -1.75,-0.95 1.75,0.95, height 1.9
1210_210L [mm] "1210"
  rect 1.1x2.6 smd: 1(-1.35,0) 2(1.35,0)
  silkscreen extent -0.4,-1.2 0.4,1.2, body extent -1.7,-1.35 1.7,1.35, height 2.1
1210_270L [mm] "1210"
  rect 1.1x2.6 smd: 1(-1.35,0) 2(1.35,0)
  silkscreen extent -0.4,-1.2 0.4,1.2, body extent -1.7,-1.35 1.7,1.35, height 2.7
2220_280L [mm] "Chip Capacitor, Body 5.7x5.0mm, IPC High Density"
  rect 1.4x5.2 smd: 1(-2.5,0) 2(2.5,0)
  silkscreen extent -1.4,-2.5 1.4,2.5, body extent -2.95,-2.6 2.95,2.65, height 2.8
AssemblyNote [mil] "Assembly Note"
AssemblyNoteLabel [mil] "Assembly Note for PCB Labels"
CE_Mark_5mm [mil] "Minimum text height for CE Mark"
  silkscreen extent -138,-98 138,98
CRE2512-R5_R9 [mm] "SMD, 2-Leads, Body 6.45x3.35mm, Pitch 6.2mm"
  rect 2.1x4 smd: 1(-3.1,0) 2(3.1,0)
  silkscreen extent -1.6,-1.78 1.6,1.78, body extent -3.32,-1.77 3.32,1.77, height 0.9
DBZ0003A-MFG [mm]
  rrect17% 1.3x0.6 smd paste+0 mask+0: 1(-1.05,0.95) 2(-1.05,-0.95) 3(1.05,0)
  silkscreen extent -0.7,-1.52 0.7,1.52, body extent -1.8,-1.62 1.8,1.62, height 0.25
DCY0004A_N [mm] "SOT223/SC73, 4-Leads, Body 6.5x3.5mm, Pitch 2.3mm, Lead Span 7mm, IPC Medium Density"
  rrect11% 1.75x0.9 smd: 1(-3.125,2.3) 2(-3.125,0) 3(-3.125,-2.3)
  rrect6% 1.75x3.2 smd: 4(3.125,0)
  silkscreen extent -3.02,-3.35 1.4,3.47, body extent -3.48,-3.25 3.48,3.25, height 1.68
DDA0008E_N [mm]
  rrect17% 1.45x0.6 smd: 1(-2.725,1.905) 2(-2.725,0.635) 3(-2.725,-0.635) 4(-2.725,-1.905) 5(2.725,-1.905) 6(2.725,-0.635) 7(2.725,0.635) 8(2.725,1.905)
  rrect4% 2.4x3.1 on Top Paste: 9(0,0)
  rrect7% 2.95x4.9 smd paste-1.5 mask-1.5: 9(0,0)
  rrect4% 2.4x3.1 on Top Solder: 9(0,0)
  silkscreen extent -3.22,-2.5 1.4,2.5, body extent -3,-2.45 3,2.45, height 1.57
DDPAK [mil] "D2-PAK, 3-Pads, Body 9.7x10.4mm (max), TO-263AB, using Vishay Silionix recommended pad sizes"
  rrect8% 135x49.49 smd: 1(-246.06,100) 3(-246.06,-100)
  rrect1% 355x420 smd paste-181.1: 2(155.51,0)
  body extent -295,-202 324,202, height 180
DRY0006A [mm] "USON-6"
  rrect67% 0.45x0.3 smd paste-0.05 mask-0.05: 1(-0.275,0.5)
  rrect67% 0.4x0.3 smd paste-0.05 mask-0.05: 2(-0.3,0) 3(-0.3,-0.5) 4(0.3,-0.5) 5(0.3,0) 6(0.3,0.5)
  body extent -0.5,-0.72 0.5,0.73, height 0.58
FCC_disclaimer [mil]
Fiducial10-20 [mm]
  round 1 smd mask+0.5: 1(0,0)
  Top Layer keep-out circle w1.178: c0,0 r0.5
FP-CPF-A-0603B10RE_0603-MFG [mm]
  rrect11% 1x0.9 smd paste+0 mask+0: 1(-0.9,0) 2(0.9,0)
  silkscreen extent 0,-0.45 0,0.45, body extent -1.5,-0.55 1.5,0.55, height 0.25
FP-CRCW12060000Z0EAC_1206-MFG [mm]
  rrect11% 0.9x1.7 smd paste+0 mask+0: 1(-1.45,0) 2(1.45,0)
  silkscreen extent -0.63,-0.82 0.63,0.82, body extent -2,-0.95 2,0.95, height 0.25
FP-ESH477M100AM2AA_RADIAL-MFG [mm]
  rrect7% 1.45x1.45 hole 0.95 paste-1000 mask+0: 1(-3.75,0)
  round 1.45 hole 0.95 paste-1000 mask+0: 2(3.75,0)
  silkscreen extent -8.25,-8.25 8.25,8.25, body extent -8.35,-8.35 8.35,8.35, height 0.25
FP-RL1220S-R75-F_0805-IPC_A [mil]
  rrect7% 53.34x61.27 smd paste+0 mask+0: 1(-38.41,0) 2(38.41,0)
  silkscreen extent -65,-46 65,46, body extent -85,-50 85,50, height 10
Fuse_0463 [mm] "SMD, 2-Leads, Body 10.1x3.12mm"
  rrect3% 3.25x3.43 smd: 1(-4.675,0) 2(4.675,0)
  silkscreen extent -2.6,-1.5 2.6,1.5, body extent -5.05,-1.56 5.05,1.56, height 3.12
Harwin_D3082-05 [mm] "Shorting Plug, 10.16mm spacing, TH"
  round 1.8 hole 1.3: 1(-5.08,0) 2(5.08,0)
  silkscreen extent -3.9,-0.53 3.9,0.53, body extent -5.6,-0.52 5.61,0.52, height 6.63
IEC_HighVoltage_Small [mil]
  silkscreen extent -107,-88 107,97
IEC_HotSurface_Small [mil]
  silkscreen extent -107,-93 107,92
Keystone_1902E [mil] "Hex Standoff, 4-40 threaded, nylon"
  round 1 on Mech3: 0(0,0)
  body extent -145,-126 146,126, height 1001
LED_LTST-C170_Red [mm] "LITE-ON"
  rect 1.2x1.2 smd: 1(-1.05,0) 2(1.05,0)
  silkscreen extent -1.6,-1 2.2,1, body extent -1.05,-0.67 1.05,0.67, height 1.1
LED_LTST-C171 [mm] "LITE-ON"
  rect 1.2x1.2 smd: 1(-1.05,0) 2(1.05,0)
  silkscreen extent -1.6,-1 2.2,1, body extent -1.05,-0.67 1.05,0.67, height 0.8
Net-Tie_20milWide_60milLong [mil] "20mil net tie, no solder mask opening, no solder paste"
  rect 60x20 smd paste-10 mask-10: 1(-30,0) 2(30,0)
"NY PMS 440 0025 PH" [mm] "4-40 nylon screw and mounting hole"
  round 8 hole 3.2: 1(0,0)
  body extent -3.31,-3.3 3.3,3.3, height 2.69
Phoenix_1792892 [mm] "Terminal Block, 5mm, 5x1, R/A, TH"
  rrect50% 1.7x1.7 hole 1.2: 1(-10,0)
  round 1.7 hole 1.2: 2(-5,0) 3(0,0) 4(5,0) 5(10,0)
  silkscreen extent -12.8,-4.95 12.5,5.55, body extent -12.5,-4.95 12.5,5.55, height 13.6
Phoenix_1902547 [mm] "TH, 2-Leads, Body 19.04x16mm, Pitch 9.52mm"
  rect 1.8x1.8 hole 1.3: 1(-4.76,3.1)
  round 1.8 hole 1.3: 2(4.76,3.1)
  silkscreen extent -10,-8 10.09,8, body extent -9.52,-8 10.09,8, height 22
Phoenix_1904150 [mm] "TH, 3-Leads, Body 28.56x16mm, Pitch 9.52mm"
  rect 1.8x1.8 hole 1.3: 1(-9.52,3.1)
  round 1.8 hole 1.3: 2(0,3.1) 3(9.52,3.1)
  silkscreen extent -14.8,-8 14.85,8, body extent -14.28,-8 14.85,8, height 22
PHP0048P-MFG [mm]
  rrect33% 1.6x0.3 smd paste+0 mask+0: 1(-4.25,2.75) 2(-4.25,2.25) 3(-4.25,1.75) 4(-4.25,1.25) 5(-4.25,0.75) 6(-4.25,0.25) 7(-4.25,-0.25) 8(-4.25,-0.75) 9(-4.25,-1.25) 10(-4.25,-1.75) 11(-4.25,-2.25) 12(-4.25,-2.75) 25(4.25,-2.75) 26(4.25,-2.25) 27(4.25,-1.75) 28(4.25,-1.25) 29(4.25,-0.75) 30(4.25,-0.25) 31(4.25,0.25) 32(4.25,0.75) 33(4.25,1.25) 34(4.25,1.75) 35(4.25,2.25) 36(4.25,2.75)
  rrect33% 0.3x1.6 smd paste+0 mask+0: 13(-2.75,-4.25) 14(-2.25,-4.25) 15(-1.75,-4.25) 16(-1.25,-4.25) 17(-0.75,-4.25) 18(-0.25,-4.25) 19(0.25,-4.25) 20(0.75,-4.25) 21(1.25,-4.25) 22(1.75,-4.25) 23(2.25,-4.25) 24(2.75,-4.25) 37(2.75,4.25) 38(2.25,4.25) 39(1.75,4.25) 40(1.25,4.25) 41(0.75,4.25) 42(0.25,4.25) 43(-0.25,4.25) 44(-0.75,4.25) 45(-1.25,4.25) 46(-1.75,4.25) 47(-2.25,4.25) 48(-2.75,4.25)
  rrect2% 6.5x6.5 smd paste-1000 mask-1000: 49(0,0)
  silkscreen extent -5.82,-4.1 4.1,4.1, body extent -5.15,-5.15 5.15,5.15, height 0.25
Samtec_SSQ-110-03-x-D [mm] "Receptacle, 2.54mm, 10x2, TH"
  rect 1.55x1.55 hole 1.02: 1(-11.43,1.27)
  round 1.55 hole 1.02: 2(-11.43,-1.27) 3(-8.89,1.27) 4(-8.89,-1.27) 5(-6.35,1.27) 6(-6.35,-1.27) 7(-3.81,1.27) 8(-3.81,-1.27) 9(-1.27,1.27) 10(-1.27,-1.27) 11(1.27,1.27) 12(1.27,-1.27) 13(3.81,1.27) 14(3.81,-1.27) 15(6.35,1.27) 16(6.35,-1.27) 17(8.89,1.27) 18(8.89,-1.27) 19(11.43,1.27) 20(11.43,-1.27)
  silkscreen extent -12.95,-2.48 12.95,3, body extent -12.95,-2.48 12.95,2.48, height 8.51
SDR1006 [mm] "Bourns recommended land pattern"
  oval 3.6x10 smd: 1(-3.2,0) 2(3.2,0)
  rect 2x2 smd: 1(-2.4,4) 1(-2.4,-4) 2(2.4,4) 2(2.4,-4)
  silkscreen extent -5.4,-5.43 5.4,5.43, body extent -4.9,-4.9 4.86,4.88, height 5.8
SNT-100-BK-G [mil] "Samtec STEP model"
  round 1 on Mech3: 0(0,0)
  body extent -100,-50 100,50, height 344
Sullins_PBC02SAAN [mm] "Sullins 100mil, 1x2, 230 mil above insulator"
  rect 1.65x1.65 hole 1.016: 1(0,1.27)
  round 1.65 hole 1.016: 2(0,-1.27)
  silkscreen extent -1.37,-2.54 1.27,3.1, body extent -1.27,-2.54 1.27,2.54, height 8.38
Testpoint_Keystone_Compact [mil] "Compact SMT test point"
  rect 185x135 smd: 1(0,0)
  silkscreen extent -110,-80 110,80, body extent -75,-56 75,56, height 91
Testpoint_Keystone_Miniature [mil] "Miniature SMT test point"
  rect 135x70 smd: 1(0,0)
  silkscreen extent -78,-46 78,45, body extent -52,-20 52,20, height 61
TI_Stacked_Overlay_Small [mil]
  silkscreen extent -418,-98 418,98
WEEE_Minimum [mil] "WEEElie bin"
  silkscreen extent -95,-172 99,104
WURTH_61300311121 [mm] "Header, 2.54mm, 3x1, TH"
  rrect50% 1.65x1.65 hole 1.15: 1(-2.54,0)
  round 1.65 hole 1.15: 2(0,0) 3(2.54,0)
  body extent -3.81,-1.27 3.81,1.27, height 8.54

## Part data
3.3V GVDD PVDD: library part CMP-0002830-3, "LED, Green, SMD", Color=green, Manufacturer=Lite-On, PartNumber=LTST-C171GKT, Value1=W, Value2=2.1V
3.3V_EXT 5V_EXT GHA GHB GHC GLA GLB GLC HALL_EXT PVDD_EXT VREF_EXT: library part CMP-0055152-2, "Test Point, Miniature, SMT", Manufacturer="Keystone Electronics", Supplier Part Number 1=36-5015TR-ND
C1 C3 C4 C6 C7 C8 C18 C20 C44: library part CMP-0861070-2, "CAP, CERM, 1 µF, 100 V,+/- 10%, X7R, AEC-Q200 Grade 1, 0805", Cap_Case=0805, Manufacturer=AVX, TempCo=X7R, Tolerance_%=10%, Value2=100V, ValueDisplayed=1µF
C2: library part CMP-0064964-2, "CAP, CERM, 10 uF, 100 V,+/- 10%, X7S, AEC-Q200 Grade 1, 2220", Cap_Case=2220, Manufacturer=TDK, Supplier Part Number 1=445-8768-1-ND, TempCo=X7S, Tolerance_%=10%, Value1=Unknown, Value2=100V, ValueDisplayed=10uF
C5: library part CMP-0079201-1, "CAP, CERM, 10 µF, 50 V,+/- 10%, X7R, 1210", Cap_Case=1210, Manufacturer="Samsung Electro-Mechanics", Supplier Part Number 1=1276-3388-1-ND, TempCo=X7R, Tolerance_%=10%, Value1="0.005 ohm", Value2=50V, ValueDisplayed=10µF
C9: library part CMP-0006263-2, "CAP, CERM, 2.2 uF, 10 V, +/- 10%, X5R, 0402", Cap_Case=0402, Manufacturer=TDK, Supplier Part Number 1=445-7392-1-ND, TempCo=X5R, Tolerance_%=10%, Value1=Unknown, Value2=10V, ValueDisplayed=2.2uF
C11 C22: library part CMP-0007085-4, "CAP, CERM, 2200 pF, 100 V, +/- 10%, X7R, AEC-Q200 Grade 1, 0603", Cap_Case=0603, Manufacturer=TDK, Supplier Part Number 1=445-5808-1-ND, TempCo=X7R, Tolerance_%=10%, Value1="0.923948 ohm", Value2=100V, ValueDisplayed=2200pF
C12 C13 C14 C24 C25 C26: library part CMP-0007475-4, "CAP, CERM, 2200 pF, 100 V, +/- 10%, X7R, 0603", Cap_Case=0603, Manufacturer=MuRata, Supplier Part Number 1=490-1478-1-ND, TempCo=X7R, Tolerance_%=10%, Value1=Unknown, Value2=100V, ValueDisplayed=2200pF
C15 C17 C19 C27 C28 C29: library part CMP-0006737-4, "CAP, CERM, 2200 pF, 100 V, +/- 10%, X7R, 0603", Cap_Case=0603, Manufacturer=AVX, Supplier Part Number 1=478-1201-1-ND, TempCo=X7R, Tolerance_%=10%, Value1="0.192 ohm", Value2=100V, ValueDisplayed=2200pF
C16: library part CMP-0007575-3, "CAP, CERM, 0.33 uF, 25 V, +/- 10%, X5R, 0805", Cap_Case=0805, Manufacturer=AVX, Supplier Part Number 1=478-1406-1-ND, TempCo=X5R, Tolerance_%=10%, Value1="0.02 ohm", Value2=25V, ValueDisplayed=0.33uF
C21: library part CMP-0009084-2, "CAP, CERM, 2.2 uF, 100 V, +/- 10%, X7R, 1210", Cap_Case=1210, Manufacturer=Kemet, Supplier Part Number 1=399-5511-2-ND, TempCo=X7R, Tolerance_%=10%, Value1=Unknown, Value2=100V, ValueDisplayed=2.2uF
